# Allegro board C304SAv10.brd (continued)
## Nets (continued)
GNDD: C1.2 C2.2 C3.2 C4.2 C5.1 C6.1 C7.1 C8.2 C9.2 C10.1 C11.1 C12.1 C13.1 C14.2 C15.1 C16.1 C17.1 C18.1 C19.1 C20.2 C21.2 C22.2 C23.2 C24.2 C25.2 C26.2 C27.2 C28.2 C29.2 C30.2 C31.2 C32.2 C33.2 C34.2 C35.2 C36.2 C37.2 C38.2 C39.2 C40.2 C41.2 C42.2 C43.2 C44.2 C45.2 C46.2 C47.2 C48.2 C49.2 C50.2 C51.2 C52.2 C53.2 C54.2 C55.2 C56.2 C57.2 C58.2 C59.2 C60.2 C61.2 C62.2 C63.2 C64.2 C65.2 C68.2 C69.2 C70.2 C71.1 C72.1 C73.2 C74.2 C75.2 C76.2 C77.2 C78.1 C79.1 C80.2 C81.2 C82.2 C83.2 C84.2 C85.2 C86.2 C87.2 C88.2 C89.2 C90.2 C91.2 C92.2 C93.2 C94.2 C95.2 C96.2 C97.2 C98.2 C99.2 C100.2 C101.2 C102.2 C103.2 C104.2 C105.2 C106.2 C107.2 C108.2 C109.2 C110.2 C111.2 C112.2 C113.2 C114.2 C115.2 C116.2 C117.2 C118.2 C119.2 C120.2 C121.2 C122.2 C123.2 C124.2 C125.2 C126.2 C127.2 C128.2 C129.2 C130.2 C131.2 C132.2 C134.2 C135.2 C136.2 C137.2 C138.2 C139.2 C140.2 C141.2 C142.2 C143.2 C148.2 C151.2 C154.2 C155.2 C156.2 C157.2 C160.2 C163.2 C164.2 C165.2 C168.2 C171.2 C172.2 C173.2 C176.2 C179.2 C182.2 C184.2 C185.2 C186.2 C187.2 C188.2 C189.2 C190.2 C191.2 C192.2 C193.2 C194.2 C195.2 C196.2 C197.2 C198.2 C199.2 C200.2 C201.2 C202.2 C203.2 C204.2 C205.2 C206.2 C207.2 C208.2 C209.2 C210.2 C211.2 C212.2 C213.2 C214.2 C215.1 C216.1 C217.1 C218.1 C219.2 C220.2 C222.2 C223.2 C380.2 C381.2 C382.2 C383.2 C384.2 C385.2 C386.2 C387.2 C388.2 CE1.2 CE2.2 CE3.2 CE4.2 CE11.2 D1.8(GND#8) D1.20(GND#20) D1.27(GND#27) D1.30(GNDPLL#30) D1.34(GNDOSC) D1.39(GNDPLL#39) D1.41(GND#41) D1.57(GND#57) D1.63(GND#63) D1.76(GND#76) D1.94(GND#94) D1.112(GND#112) D1.117(GND#117) D1.130(GND#130) D1.132(GND#132) D1.147(GND#147) D1.153(GND#153) D1.165(GND#165) D1.184(GND#184) D1.189(GND#189) D1.200(GND#200) D2.1(A0) D2.2(A1) D2.3(A2) D2.4(VSS) D2.7(TSET) D3.3(GND) D4.1(GND) D5.6(VSSQ#6) D5.12(VSSQ#12) D5.28(VSS#28) D5.41(VSS#41) D5.46(VSSQ#46) D5.52(VSSQ#52) D5.54(VSS#54) D6.6(VSSQ#6) D6.12(VSSQ#12) D6.28(VSS#28) D6.41(VSS#41) D6.46(VSSQ#46) D6.52(VSSQ#52) D6.54(VSS#54) D7.27(VSS#27) D7.46(VSS#46) D8.11(DGND#11) D8.17(DGND#17) D8.29(AGND#29) D8.35(AGND#35) D8.45(DGND#45) D9.AA2(GND#AA2) D9.AA9(GNDA#AA9) D9.AA20(GNDA#AA20) D9.AA27(GND#AA27) D9.AC6(GND#AC6) D9.AC9(GND#AC9) D9.AC13(GND#AC13) D9.AC16(GND#AC16) D9.AC20(GND#AC20) D9.AC23(GND#AC23) D9.AF1(GND#AF1) D9.AF28(GND#AF28) D9.AG2(GND#AG2) D9.AG5(GND#AG5) D9.AG9(GND#AG9) D9.AG13(GND#AG13) D9.AG16(GND#AG16) D9.AG20(GND#AG20) D9.AG24(GND#AG24) D9.AG27(GND#AG27) D9.B2(GND#B2) D9.B5(GND#B5) D9.B9(GND#B9) D9.B13(GND#B13) D9.B16(GND#B16) D9.B20(GND#B20) D9.B24(GND#B24) D9.B27(GND#B27) D9.C1(GND#C1) D9.C28(GND#C28) D9.F6(GND#F6) D9.F9(GND#F9) D9.F13(GND#F13) D9.F16(GND#F16) D9.F20(GND#F20) D9.F23(GND#F23) D9.H2(GND#H2) D9.H9(GNDA#H9) D9.H20(GNDA#H20) D9.H27(GND#H27) D9.J11(GND#J11) D9.J18(GND#J18) D9.K6(GND#K6) D9.K10(GND#K10) D9.K12(GND#K12) D9.K14(GND#K14) D9.K16(GND#K16) D9.K18(GND#K18) D9.K20(GND#K20) D9.K23(GND#K23) D9.L9(GND#L9) D9.L11(GND#L11) D9.L13(GND#L13) D9.L15(GND#L15) D9.L17(GND#L17) D9.L19(GND#L19) D9.M10(GND#M10) D9.M12(GND#M12) D9.M14(GND#M14) D9.M16(GND#M16) D9.M18(GND#M18) D9.M20(GND#M20) D9.M22(MSEL2) D9.N2(GND#N2) D9.N6(GND#N6) D9.N9(GND#N9) D9.N11(GND#N11) D9.N13(GND#N13) D9.N15(GND#N15) D9.N17(GND#N17) D9.N19(GND#N19) D9.N22(MSEL0) D9.N23(GND#N23) D9.N27(GND#N27) D9.P10(GND#P10) D9.P12(GND#P12) D9.P14(GND#P14) D9.P16(GND#P16) D9.P18(GND#P18) D9.P20(GND#P20) D9.P22(MSEL3) D9.P23(MSEL1) D9.R8(NCE) D9.R9(GND#R9) D9.R11(GND#R11) D9.R13(GND#R13) D9.R15(GND#R15) D9.R17(GND#R17) D9.R19(GND#R19) D9.T2(GND#T2) D9.T6(GND#T6) D9.T10(GND#T10) D9.T12(GND#T12) D9.T14(GND#T14) D9.T16(GND#T16) D9.T18(GND#T18) D9.T20(GND#T20) D9.T23(GND#T23) D9.T27(GND#T27) D9.U9(GND#U9) D9.U11(GND#U11) D9.U13(GND#U13) D9.U15(GND#U15) D9.U17(GND#U17) D9.U19(GND#U19) D9.V10(GND#V10) D9.V12(GND#V12) D9.V14(GND#V14) D9.V16(GND#V16) D9.V18(GND#V18) D9.V20(GND#V20) D9.W6(GND#W6) D9.W9(GND#W9) D9.W11(GND#W11) D9.W13(GND#W13) D9.W15(GND#W15) D9.W17(GND#W17) D9.W19(GND#W19) D9.W23(GND#W23) D9.Y11(GND#Y11) D9.Y18(GND#Y18) D11.3(VEE#3) D11.17(VEE#17) D12.3(VEE#3) D12.17(VEE#17) D13.3(VEE#3) D13.17(VEE#17) D14.3(VEE#3) D14.17(VEE#17) D15.3(GND#3) D15.6(GND#6) D16.1(GND) D18.15(GND) D28.3(SGND) D28.10(PGND#10) D28.11(PGND#11) D28.EP D31.4(GND#4) D31.10(GND#10) D31.15(GND#15) D31.21(GND#21) D31.28(GND#28) D31.34(GND#34) D31.39(GND#39) D31.45(GND#45) D32.4(GND#4) D32.10(GND#10) D32.15(GND#15) D32.21(GND#21) D32.28(GND#28) D32.34(GND#34) D32.39(GND#39) D32.45(GND#45) D33.1(A0) D33.2(A1) D33.3(A2) D33.4(VSS) D33.7(TEST) G1.3(GND) G2.3(GND#3) G2.4(GND#4) G2.5(GND#5) G3.3(GND) G4.2(GND) GND.1(TP) HL5.2(CATHODE) HL6.2(CATHODE) HL7.2(CATHODE) HL8.2(CATHODE) R1.2 R2.2 R3.2 R10.1 R14.1 R16.1 R28.1 R44.2 R47.2 R51.2 R53.2 R54.1 R68.2 R79.2 R82.2 R114.2 R115.2 R116.2 R117.2 R120.2 R131.1 R133.1 R134.2 R140.1 VD1.1(ANODE) X1.A20 X1.A21 X1.A30 X1.B4 X1.B8 X1.B20 X1.B21 X1.B22 X1.B26 X1.B30 X1.C6 X1.C8 X1.C9 X1.C17 X1.C20 X1.C21 X1.C22 X1.C26 X1.C30 X3.2 X4.1 X5.2 X5.4 X5.6 X5.8 X5.10 X5.14 X6.9(GND#9) X6.10(GND#10) X7.2 X7.10 X8.1(GND) X9.1(GND) X10.1(GND) X11.1(GND) X12.1(GND) X13.1(GND) X14.2(GND#2) X14.3(GND#3) X14.4(GND#4) X15.2(GND#2) X15.3(GND#3) X15.4(GND#4) X16.2(GND#2) X16.3(GND#3) X16.4(GND#4) X17.2(GND#2) X17.3(GND#3) X17.4(GND#4) X18.2
27M_FPGA: D9.Y28(CLK7/DIFFCLK_3N) R69.2
706MR: C9.1 D1.74(PA28) D3.1(M\R\) R11.1 X3.1
706WDI: D1.73(PA27) D3.6(WDI)
ASI_OUTN1: C150.1 D9.D1(IO/DIFFIO_L2N) R76.2
ASI_OUTN2: C162.1 D9.G1(IO/DIFFIO_L11N) R93.2
ASI_OUTN3: C170.1 D9.W1(IO/DIFFIO_L24N) R101.2
ASI_OUTN4: C178.1 D9.AC1(IO/DIFFIO_L27N) R109.2
ASI_OUTP1: C149.1 D9.D2(IO/DIFFIO_L2P) R76.1
ASI_OUTP2: C161.1 D9.G2(IO/DIFFIO_L11P) R93.1
ASI_OUTP3: C169.1 D9.W2(IO/DIFFIO_L24P) R101.1
ASI_OUTP4: C177.1 D9.AC2(IO/DIFFIO_L27P) R109.1
AT91_CAS: D1.177(CAS) D5.17(C\A\S\) D6.17(C\A\S\)
AT91_NCS0: D1.166(NCS0) D7.26(C\E\)
AT91_NCS1: D1.167(NCS1/SDCS) D5.19(C\S\) D6.19(C\S\)
AT91_NCS7: D1.14(NCS7) D9.AG26(IO/DIFFIO_B41P)
AT91_NRD: D1.170(NRD) D7.28(O\E\) D9.AH11(IO/DIFFIO_B19N)
AT91_NWE: D1.171(NWE) D7.11(W\E\) D9.AG12(IO/DIFFIO_B21P)
AT91_RAS: D1.176(RAS) D5.18(R\A\S\) D6.18(R\A\S\)
AT91_SDCKE: D1.175(SDCKE) D5.37(CKE) D6.37(CKE)
AT91_SDCLK: D1.174(SDCK) R35.2 R36.2
AT91_SDWE: D1.178(SDWE) D5.16(W\E\) D6.16(W\E\)
AT91A0: D1.133(N0/NBS0) D5.15(LDQM)
AT91A1: D1.134(N1/NBS2) D6.15(LDQM) D7.25(A0) D9.W27(IO/DIFFIO_R25N)
AT91A2: D1.135(A2) D5.23(A0) D6.23(A0) D7.24(A1) D9.AC27(IO/DIFFIO_R31P)
AT91A3: D1.136(A3) D5.24(A1) D6.24(A1) D7.23(A2) D9.AC28(IO/DIFFIO_R31N)
AT91A4: D1.137(A4) D5.25(A2) D6.25(A2) D7.22(A3) D9.AB27(IO/DIFFIO_R28P)
AT91A5: D1.138(A5) D5.26(A3) D6.26(A3) D7.21(A4) D9.AB28(IO/DIFFIO_R28N)
AT91A6: D1.139(A6) D5.29(A4) D6.29(A4) D7.20(A5) D9.AD28(IO/DIFFIO_R33N)
AT91A7: D1.140(A7) D5.30(A5) D6.30(A5) D7.19(A6) D9.AD27(IO/DIFFIO_R33P)
AT91A8: D1.141(A8) D5.31(A6) D6.31(A6) D7.18(A7) D9.AE28(IO/DIFFIO_R34N)
AT91A9: D1.142(A9) D5.32(A7) D6.32(A7) D7.8(A8) D9.AE27(IO/DIFFIO_R34P)
AT91A10: D1.143(A10) D5.33(A8) D6.33(A8) D7.7(A9) D9.AD24(IO/DIFFIO_B40N)
AT91A11: D1.145(A11) D5.34(A9) D6.34(A9) D7.6(A10)
AT91A12: D1.148(A12) D7.5(A11)
AT91A13: D1.149(A13) D5.35(A11) D6.35(A11) D7.4(A12)
AT91A14: D1.150(A14) D5.36(NC1) D6.36(NC1) D7.3(A13)
AT91A15: D1.151(A15) D7.2(A14)
AT91A16: D1.154(A16/BA0) D5.20(BA0) D6.20(BA0) D7.1(A15)
AT91A17: D1.155(A17/BA1) D5.21(BA1) D6.21(BA1) D7.48(A16)
AT91A18: D1.156(A18) D7.17(A17)
AT91A19: D1.157(A19) D7.16(A18)
AT91A20: D1.158(A20) D7.9(NC/A19)
AT91A21: D1.159(A21) D7.10(NC/A20)
AT91A22: D1.160(A22) D7.13(NC/A21)
AT91D0: D1.179(D0) D5.2(DQ0) D7.29(DQ0) D9.AH12(IO/DIFFIO_B21N)
AT91D1: D1.180(D1) D5.4(DQ1) D7.31(DQ1) D9.AG17(IO/DIFFIO_B24P)
AT91D2: D1.181(D2) D5.5(DQ2) D7.33(DQ2) D9.AH17(IO/DIFFIO_B24N)
AT91D3: D1.182(D3) D5.7(DQ3) D7.35(DQ3) D9.AF18(IO/DIFFIO_B31N)
AT91D4: D1.185(D4) D5.8(DQ4) D7.38(DQ4) D9.AH18(IO/DIFFIO_B27N)
AT91D5: D1.186(D5) D5.10(DQ5) D7.40(DQ5) D9.AG18(IO/DIFFIO_B27P)
AT91D6: D1.187(D6) D5.11(DQ6) D7.42(DQ6) D9.AG23(IO/DIFFIO_B33P)
AT91D7: D1.190(D7) D5.13(DQ7) D7.44(DQ7) D9.AG22(IO/DIFFIO_B32P)
AT91D8: D1.191(D8) D5.42(DQ8) D7.30(DQ8) D9.AH19(IO/DIFFIO_B28N)
AT91D9: D1.192(D9) D5.44(DQ9) D7.32(DQ9) D9.AG19(IO/DIFFIO_B28P)
AT91D10: D1.193(D10) D5.45(DQ10) D7.34(DQ10) D9.AH21(IO/DIFFIO_B30N)
AT91D11: D1.194(D11) D5.47(DQ11) D7.36(DQ11) D9.AG21(IO/DIFFIO_B30P)
AT91D12: D1.195(D12) D5.48(DQ12) D7.39(DQ12) D9.AH22(IO/DIFFIO_B32N)
AT91D13: D1.196(D13) D5.50(DQ13) D7.41(DQ13) D9.AH23(IO/DIFFIO_B33N)
AT91D14: D1.197(D14) D5.51(DQ14) D7.43(DQ14) D9.AH25(IO/DIFFIO_B39N)
AT91D15: D1.198(D15) D5.53(DQ15) D7.45(DQ15) D9.AG25(IO/DIFFIO_B39P)
AT91D16: D1.201(D16) D6.2(DQ0)
AT91D17: D1.202(D17) D6.4(DQ1)
AT91D18: D1.203(D18) D6.5(DQ2)
AT91D19: D1.204(D19) D6.7(DQ3)
AT91D20: D1.205(D20) D6.8(DQ4)
AT91D21: D1.206(D21) D6.10(DQ5)
AT91D22: D1.207(D22) D6.11(DQ6)
AT91D23: D1.208(D23) D6.13(DQ7)
AT91D24: D1.1(D24) D6.42(DQ8)
AT91D25: D1.2(D25) D6.44(DQ9)
AT91D26: D1.3(D26) D6.45(DQ10)
AT91D27: D1.4(D27) D6.47(DQ11)
AT91D28: D1.5(D28) D6.48(DQ12)
AT91D29: D1.6(D29) D6.50(DQ13)
AT91D30: D1.9(D30) D6.51(DQ14)
AT91D31: D1.10(D31) D6.53(DQ15)
AT91NBS1: D1.172(NBS1) D5.39(UDQM)
AT91NBS3: D1.173(NBS3) D6.39(UDQM)
AT91NRST: C2.1 D1.115(NRST) D3.7(RESET) R9.2 X5.12
AT91NTRST: D1.110(NTRST) R29.1 X5.3
AT91SDA10: D1.144(SDA10) D5.22(A10/AP) D6.22(A10/AP)
AT91TCK: D1.108(TCK) R32.1 X5.9
AT91TDI: D1.106(TDI) R30.1 X5.5
AT91TDO: D1.107(TDO) R34.1 X5.11
AT91TMS: D1.109(TMS) R31.1 X5.7
BOARDDET_0: R1.1 X1.A32
BOARDDET_1: R2.1 X1.B32
BOARDDET_2: R3.1 X1.C32
E3.3VA: C75.1 C76.1 C77.1 D8.36(AVDD33) D8.48(DVDD33#48) L2.2
ENETCOL: D1.100(ECOL) D8.1(COL)
ENETCRS: D1.53(ECRS) D8.23(CRS)
ENETMDC: D1.59(EMDC) D8.25(MDC)
ENETMDIO: D1.60(EMDIO) D8.26(MDIO) R8.2
ENETRX0: D1.54(ERX0) D8.21(RXD0)
ENETRX1: D1.55(ERX1) D8.20(RXD1)
ENETRX2: D1.97(ERX2) D8.19(RXD2)
ENETRX3: D1.98(ERX3) D8.18(RXD3)
ENETRX+: D8.31(TPRX+) R55.2 T1.6(RD+)
ENETRX-: D8.30(TPRX-) R52.2 T1.8(RD-)
ENETRXCK: D1.101(ERXCK) D8.16(RXC)
ENETRXDV: D1.99(ERXDV) D8.22(RXDV)
ENETRXER: D1.58(ERXER) D8.24(RXER/FXEN) R140.2
ENETTX0: D1.51(ETX0) D8.6(TXD0)
ENETTX1: D1.52(ETX1) D8.5(TXD1)
ENETTX2: D1.92(ETX2) D8.4(TXD2)
ENETTX3: D1.95(ETX3) D8.3(TXD3)
ENETTX+: D8.34(TPTX+) R57.2 T1.1(TD+)
ENETTX-: D8.33(TPTX-) R56.2 T1.3(TD-)
ENETTXCK: D1.49(ETXCK) D8.7(TXCLK)
ENETTXEN: D1.50(ETXEN) D8.2(TXEN)
F_LED0: D9.AB23(IO/RDN3) HL10.2(CATHODE)
F_LED1: D9.AC26(IO/DIFFIO_R35P) HL11.2(CATHODE)
F_LED2: D9.AC24(IO/DIFFIO_R36P) HL12.2(CATHODE)
F_LED3: D9.AD26(IO/DIFFIO_R35N) HL9.2(CATHODE)
FPGA_CONDONE: D9.P24(CONF_DONE) R65.1 R121.2 R129.1
FPGA_DATA0: D9.N7(IO/DATA0) R124.2 R126.1 R136.1
FPGA_DCLK: D9.P3(DCLK) R123.2 R128.1 R135.1
FPGA_INT: D1.45(IRQ5/PA3) D9.AH26(IO/DIFFIO_B41N)
FPGA_NCONFIG: C220.1 D9.P4(NCONFIG) R122.2 R127.1 R146.1
FPGA_NSTATUS: D9.M6(NSTATUS) R64.1 R125.2 R130.1
FPGA_TCK: D9.P5(TCK) R68.1 X7.1
FPGA_TDI: D9.P7(TDI) R67.1 X7.9
FPGA_TDO: D9.P6(TDO) X7.3
FPGA_TMS: D9.P8(TMS) R66.1 X7.5
HS_ADDB_A0: D9.U27(IO_3_B5) X1.A19
HS_ADDB_A1: D9.V28(IO/DIFFIO_R24N) X1.B19
HS_ADDB_A2: D9.V27(IO/DIFFIO_R24P) X1.C19
HS_ADDB_A3: D9.R28(IO/DIFFIO_R18N) X1.A18
HS_ADDB_A4: D9.R27(IO/DIFFIO_R18P) X1.B18
HS_ADDB_A5: D9.U28(IO/DIFFIO_R21N) X1.C18
HS_ADDB_A6: D9.M27(IO/DIFFIO_R14P) X1.A17
HS_ADDB_A7: D9.M28(IO/DIFFIO_R14N) X1.B17
HS_DATB_D0: D9.L26(IO_1_B6) X1.A16
HS_DATB_D1: D9.M25(IO/DIFFIO_R13P) X1.B16
HS_DATB_D2: D9.M26(IO/DIFFIO_R13N) X1.C16
HS_DATB_D3: D9.K25(IO/DIFFIO_R7P) X1.A15
HS_DATB_D4: D9.K26(IO/DIFFIO_R7N) X1.B15
HS_DATB_D5: D9.L25(IO_2_B6) X1.C15
HS_DATB_D6: D9.D25(IO/DIFFIO_T38N) X1.A14
HS_DATB_D7: D9.C25(IO/DIFFIO_T38P) X1.B14
HS_DATB_D8: D9.C26(IO/DIFFIO_T42N) X1.C14
HS_DATB_D9: D9.D22(IO/DIFFIO_T41N) X1.A13
HS_DATB_D10: D9.D24(IO/DIFFIO_T36P) X1.B13
HS_DATB_D11: D9.C24(IO/DIFFIO_T36N) X1.C13
HS_DATB_D12: D9.A26(IO/DIFFIO_T40N) X1.A12
HS_DATB_D13: D9.D21(IO/DIFFIO_T35P) X1.B12
HS_DATB_D14: D9.C22(IO/DIFFIO_T35N) X1.C12
HS_DATB_D15: D9.B26(IO/DIFFIO_T42P) X1.A11
HS_ENC_RXD: D9.A23(IO/DIFFIO_T37N) X1.A9
HS_ENC_SCK: D9.B25(IO_1_B7) X1.B9
HS_ENC_TXD: D9.B23(IO/DIFFIO_T37P) X1.A8
HS_FPGA_CS: D9.D20(IO/DIFFIO_T30P) X1.A10
HS_FPGA_INT: D9.W28(IO/DIFFIO_R25P) R120.1 X1.A5
HS_FPGA_RD: D9.A25(IO/DIFFIO_T40P) X1.B10
HS_FPGA_WR: D9.B21(IO/DIFFIO_T33P) X1.C11
HS_HPI_HBE1: D9.E21(IO/DIFFIO_T39N) X1.C10
HS_HPI_HCS: D9.E22(IO/DIFFIO_T41P) X1.B11
HS_HPI_HINT: D9.D19(IO/DIFFIO_T29P) X1.B5
HS_HPI_HRDY: D9.C19(IO/DIFFIO_T29N) X1.C5
HS_SCL: D9.AH3(IO/DIFFIO_B4P) D33.6(SCL) R144.2 X1.C31
HS_SDA: D9.AG3(IO/DIFFIO_B3N) D33.5(SDA) R143.2 X1.B31
HS_TS1_CLK: D32.14(B9) X1.A26
HS_TS1_D0: D32.2(B0) X1.A29
HS_TS1_D1: D32.3(B1) X1.B29
HS_TS1_D2: D32.5(B2) X1.C29
HS_TS1_D3: D32.6(B3) X1.A28
HS_TS1_D4: D32.8(B4) X1.B28
HS_TS1_D5: D32.9(B5) X1.C28
HS_TS1_D6: D32.11(B6) X1.A27
HS_TS1_D7: D32.12(B7) X1.B27
HS_TS1_VALID: D32.13(B8) X1.C27
HS_TS2_CLK: D31.14(B9) X1.A22
HS_TS2_D0: D31.2(B0) X1.A25
HS_TS2_D1: D31.3(B1) X1.B25
HS_TS2_D2: D31.5(B2) X1.C25
HS_TS2_D3: D31.6(B3) X1.A24
HS_TS2_D4: D31.8(B4) X1.B24
HS_TS2_D5: D31.9(B5) X1.C24
HS_TS2_D6: D31.11(B6) X1.A23
HS_TS2_D7: D31.12(B7) X1.B23
HS_TS2_VALID: D31.13(B8) X1.C23
JTAGSEL: D1.105(JTAGSEL) R10.2
KEY0: D1.17(PC0) R26.2 R119.2
KEY5: D1.24(PC5) R27.2 R118.2
LED0: D1.121(PB26) HL1.2(CATHODE)
LED1: D1.122(PB27) HL2.2(CATHODE)
LED2: D1.123(FIQ/PB28) HL3.2(CATHODE)
LED3: D1.124(IRQ0/PB29) HL4.2(CATHODE)
LED_100M: D8.13(LED3/PHYAD3) R53.1 X6.13(LAN+)
LED_LINK: D8.9(LED0/PHYAD0) R58.2 R59.1
LOOP0: D9.AH14(CLK14/DIFFCLK_6N) R72.2
LOOP1: D9.B15(CLK9/DIFFCLK_5P) R70.1
LOOP2: D9.J2(CLK0/DIFFCLK_0P) R73.1
LOOP3: D9.J27(CLK4/DIFFCLK_2P) R71.2
LOOP4: D9.AG15(CLK13/DIFFCLK_7P) R74.2
LOOP5: D9.B14(CLK11/DIFFCLK_4P) R75.2
OE1: D9.AH10(IO/DIFFIO_B16N) D32.25(O\E\2\) D32.48(O\E\1\) R163.1
OE2: D9.Y25(IO/DIFFIO_R27P) D31.25(O\E\2\) D31.48(O\E\1\) R157.1
PWFBIN: C82.1 C83.1 C84.1 D8.8(PWFBIN) L3.2
PWFBOUT: C80.1 C81.1 D8.32(PWFBOUT) L3.1
REV: D9.AG4(IO/DIFFIO_B5P) X1.A31
RST8201: D1.67(RTS0/PA21) D8.42(RESETB) R43.2
RXD_232: D1.68(RXD2/PA22) R131.2 R132.1
SCL: D2.6(SCL) R5.2 R7.1
SDA: D2.5(SDA) R4.2 R6.1
TR1: D9.AG11(IO/DIFFIO_B19P) D32.1(T/R\1\) D32.24(T/R\2\) R161.2
TR2: D9.AB26(IO/DIFFIO_R30N) D31.1(T/R\1\) D31.24(T/R\2\) R156.2
TS1_CLK: D9.AE4(IO/DIFFIO_B3P) D32.35(A9) R138.1
TS1_D0: D9.AG10(IO/DIFFIO_B16P) D32.47(A0)
TS1_D1: D9.AG8(IO/DIFFIO_B12P) D32.46(A1)
TS1_D2: D9.AH8(IO/DIFFIO_B12N) D32.44(A2)
TS1_D3: D9.AH7(IO/DIFFIO_B9N) D32.43(A3)
TS1_D4: D9.AG7(IO/DIFFIO_B9P) D32.41(A4)
TS1_D5: D9.AH6(IO/DIFFIO_B7N) D32.40(A5)
TS1_D6: D9.AG6(IO/DIFFIO_B7P) D32.38(A6)
TS1_D7: D9.AH4(IO/DIFFIO_B5N) D32.37(A7)
TS1_VALID: D9.AF4(IO/DIFFIO_B2N) D32.36(A8) R141.1
TS2_CLK: D9.F26(IO/DIFFIO_R4P) D31.35(A9) R137.1
TS2_D0: D9.Y26(IO/DIFFIO_R27N) D31.47(A0)
TS2_D1: D9.Y24(IO/DIFFIO_R32N) D31.46(A1)
TS2_D2: D9.L28(IO/DIFFIO_R12N) D31.44(A2)
TS2_D3: D9.L27(IO/DIFFIO_R12P) D31.43(A3)
TS2_D4: D9.K28(IO/DIFFIO_R10N) D31.41(A4)
TS2_D5: D9.K27(IO/DIFFIO_R10P) D31.40(A5)
TS2_D6: D9.J26(IO/DIFFIO_R9N) D31.38(A6)
TS2_D7: D9.J25(IO/DIFFIO_R9P) D31.37(A7)
TS2_VALID: D9.H26(IO/DIFFIO_R4N) D31.36(A8) R142.1
TXD_232: D1.69(TXD2/PA23) D18.11(T1IN)
N05536: D1.113(TST0) R14.2
N05538: D1.114(TST1) R16.2
N07829: C12.2 D1.32(XIN) G1.2
N08193: C8.1 D1.31(XOUT) G1.1
N08983: C17.2 D1.36(XIN32) G2.1
N09392: C14.1 D1.35(XOUT32) G2.2
N27514: C7.2 D1.38(PLLRCB) R15.2
N29811: C5.2 D1.29(PLLRCA) R13.2
N30543: C19.2 R23.1
N30727: C6.2 R13.1
N31299: C13.2 R17.1
N32037: C16.2 R22.1
N43106: D1.25(NWAIT) R24.2
N44506: D1.79(DTXD/BMS) R28.2
N118230: C46.1 D5.38(CLK) R35.1
N119725: C47.1 D6.38(CLK) R36.1
N293237: C68.1 D8.47(X2) G3.1
N294666: C69.1 D8.46(X1) G3.2
N300423: D8.44(MII/SNIB/RTT3) R45.1
N301796: D8.43(ISOLATE) R44.1
N302871: D8.41(LDPS) R46.1
N304860: D8.40(RPTR) R47.1
N306022: D8.39(SPEED) R48.1
N306487: D8.38(DUPLEX) R49.1
N307425: D8.37(ANE) R50.1
N316976: D8.28(RTSET) R51.1
N334633: C72.2 T1.5(RPCT1) T1.7(CTRD)
N338225: C71.2 R52.1 R55.1
N339802: C78.2 R56.1 R57.1
N340684: C79.2 T1.2(CTTD)
N359542: R54.2 X6.14(LAN-)
N360160: R59.2 X6.12(LINK-)
N372108: C85.1 R60.2 R61.2
N373239: C86.1 R62.2 R63.2
N373968: R60.1 T1.13(RPCT2) T1.15(CTTX)
N375126: R61.1 T1.10(CTRX)
N377910: T1.9(RX-) X6.6
N379080: T1.11(RX+) X6.3
N380455: T1.14(TX-) X6.2
N381046: T1.16(TX+) X6.1
N382236: R62.1 X6.7 X6.8
N383434: R63.1 X6.4 X6.5
N9171469: D1.71(TWD/PA25) R4.1
N9173252: D1.72(TWCK/PA26) R5.1
N9248576: C3.1 D3.8(WDO) R12.2
N9251784: R11.2 R12.1 X2.1
N14977744: C10.2 R15.1
N16808315: R26.1 R27.1 X4.2
N16825915: HL3.1(ANODE) R20.2
N16825917: HL4.1(ANODE) R21.2
N16825919: HL1.1(ANODE) R18.2
N16825921: HL2.1(ANODE) R19.2
N16864209: D11.4(RREF) R85.1
N16868983: C148.1 R77.1 R78.2
N16869942: C149.2 D11.1(SDI) R77.2
N16872327: C150.2 D11.2(\\S\D\I\) R78.1
N16882305: C153.1 L6.2 R89.2
N16882306: C152.1 L5.2 R88.2
N16882340: D11.11(\\S\D\O) L6.1 R87.2 R89.1
N16882850: D11.12(SDO) L5.1 R86.2 R88.1
N16891295: C152.2 X14.1(IN)
N16896654: C160.1 R92.2 R94.1
N16896672: C159.1 L8.2 R91.2
N16896674: C158.1 L7.2 R90.2
N16896676: D12.11(\\S\D\O) L8.1 R91.1 R97.2
N16896680: D12.12(SDO) L7.1 R90.1 R96.2
N16896682: C161.2 D12.1(SDI) R94.2
N16896719: C162.2 D12.2(\\S\D\I\) R92.1
N16896823: D12.4(RREF) R95.1
N16896879: C158.2 X15.1(IN)
N16897851: C168.1 R100.2 R102.1
N16897869: C167.1 L10.2 R99.2
N16897871: C166.1 L9.2 R98.2
N16897873: D13.11(\\S\D\O) L10.1 R99.1 R105.2
N16897877: D13.12(SDO) L9.1 R98.1 R104.2
N16897879: C169.2 D13.1(SDI) R102.2
N16897916: C170.2 D13.2(\\S\D\I\) R100.1
N16898020: D13.4(RREF) R103.1
N16898076: C166.2 X16.1(IN)
N16905369: C176.1 R108.2 R110.1
N16905379: C174.1 L12.2 R106.2
N16905381: C175.1 L11.2 R107.2
N16905399: D14.11(\\S\D\O) L12.1 R106.1 R113.2
N16905403: D14.12(SDO) L11.1 R107.1 R112.2
N16905405: C177.2 D14.1(SDI) R110.2
N16905419: C178.2 D14.2(\\S\D\I\) R108.1
N16905542: D14.4(RREF) R111.1
N16905596: C175.2 X17.1(IN)
N16942301: C133.1 D15.4(FB) R79.1 R80.2
N16942335: D15.2(VOUT) L4.1 VD1.2(CATHODE)
N16942461: D15.5(O\N\) R82.1
N16942511: HL6.1(ANODE) R81.2
N16948660: HL7.1(ANODE) R83.2
N16978661: C153.2 R114.1
N16984500: C167.2 R116.1
N16986460: C174.2 R117.1
N17223725: D1.84(PB4) R130.2
N17224583: D1.85(PB5) R129.2
N17225441: D1.86(PB6) R128.2
N17226299: D1.87(PB7) R127.2
N17227157: D1.88(PB8) R126.2
N17239189: R121.1 X1.A7
N17239190: R122.1 X1.A6
N17245894: HL8.1(ANODE) R84.2
N17253757: R123.1 X1.B7
N17253758: R124.1 X1.B6
N17260250: R125.1 X1.C7
N17338881: D18.12(R1OUT) R132.2
N17347251: D18.10(T2IN) R133.2
N17354165: C180.1 D18.5(C2-)
N17355489: C180.2 D18.4(C2+)
N17356153: C181.1 D18.3(C1-)
N17358824: C181.2 D18.1(C1+)
N17377653: C183.1 D18.2(V+)
N17383951: C184.1 D18.6(V-)
N17388205: D18.14(T1OUT) X18.1
N17389740: D18.13(R1IN) X18.3
N17391601: D18.7(T2OUT) R134.1
N17552645: C219.1 D28.4(SS)
N17552715: D28.8(SW#8) D28.9(SW#9) L13.1
N17574922: C187.1 R136.2
N17574956: G4.3(CLK_OUT) R69.1
N17575063: C186.1 R135.2
N17877624: D9.H24(IO/DIFFIO_R1N) R71.1
N17882638: D9.G15(IO_4_B7) R70.2
N17918549: C222.1 R142.2
N17918577: C223.1 R141.2
N17986390: D9.AE20(IO/DIFFIO_B36P) R74.1
N18029824: D9.AB13(IO/DIFFIO_B20N) R72.1
N18049270: D9.C13(IO/DIFFIO_T22N) R75.1
N18128293: C188.1 R137.2
N18128321: C189.1 R138.2
N18384691: HL12.1(ANODE) R139.2
N18384693: HL9.1(ANODE) R25.2
N18384695: HL10.1(ANODE) R41.2
N18384697: HL11.1(ANODE) R42.2
N18408270: HL5.1(ANODE) R33.2
N168966681: C159.2 R115.1
N176021771: D9.H6(IO1_B1) R73.2

Pads without a net: D1 11 12 13 15 16 18 21 22 23 42 43 44 46 47 48 61 64 65 66 70 77 78 80 81 82 83 89 90 91 96 102 103 104 118 119 120 125 126 127 128 161 162 163 168 169; D3 4 5; D5 40; D6 40; D7 12 14 15 47; D8 10 12 15 27; D9 A3 A4 A6 A7 A8 A10 A11 A12 A14 A15 A17 A18 A19 A21 A22 AA3 AA4 AA5 AA6 AA7 AA8 AA10 AA12 AA13 AA14 AA15 AA16 AA17 AA19 AA21 AA22 AA23 AA24 AA25 AA26 AB1 AB2 AB3 AB4 AB5 AB6 AB7 AB8 AB9 AB10 AB11 AB12 AB14 AB15 AB16 AB17 AB18 AB19 AB20 AB21 AB22 AB24 AB25 AC3 AC4 AC5 AC7 AC8 AC10 AC11 AC12 AC14 AC15 AC17 AC18 AC19 AC21 AC22 AC25 AD1 AD2 AD3 AD4 AD5 AD7 AD8 AD10 AD11 AD12 AD14 AD15 AD17 AD18 AD19 AD21 AD22 AD25 AE1 AE2 AE3 AE5 AE6 AE7 AE8 AE9 AE10 AE11 AE12 AE13 AE14 AE15 AE16 AE17 AE18 AE19 AE21 AE22 AE23 AE24 AE25 AE26 AF2 AF3 AF5 AF6 AF7 AF8 AF9 AF10 AF11 AF12 AF13 AF14 AF15 AF16 AF17 AF19 AF20 AF21 AF22 AF23 AF24 AF25 AF26 AF27 AG14 AH15 B3 B4 B6 B7 B8 B10 B11 B12 B17 B18 B19 B22 C2 C3 C4 C5 C6 C7 C8 C9 C10 C11 C12 C14 C15 C16 C17 C18 C20 C21 C23 C27 D3 D4 D5 D6 D7 D8 D9 D10 D11 D12 D13 D14 D15 D16 D17 D18 D23 D26 D27 D28 E1 E2 E3 E4 E5 E7 E8 E10 E11 E12 E14 E15 E17 E18 E19 E24 E25 E26 E27 E28 F1 F2 F3 F4 F5 F7 F8 F10 F11 F12 F14 F15 F17 F18 F19 F21 F22 F24 F25 F27 F28 G3 G4 G5 G6 G7 G8 G9 G10 G11 G12 G13 G14 G16 G17 G18 G19 G20 G21 G22 G23 G24 G25 G26 G27 G28 H3 H4 H5 H7 H8 H10 H12 H13 H14 H15 H16 H17 H19 H21 H22 H23 H25 J1 J3 J4 J5 J6 J7 J10 J12 J13 J14 J15 J16 J17 J19 J22 J23 J24 J28 K1 K2 K3 K4 K7 K8 K21 K22 L1 L2 L3 L4 L5 L6 L7 L8 L21 L22 L23 L24 M1 M2 M3 M4 M5 M7 M8 M21 M23 M24 N3 N4 N8 N21 N25 N26 P1 P2 P21 P25 P26 P27 P28 R1 R2 R3 R4 R5 R6 R7 R21 R22 R23 R24 R25 R26 T3 T4 T7 T8 T21 T22 T25 T26 U1 U2 U3 U4 U5 U6 U7 U8 U21 U22 U23 U24 U25 U26 V1 V2 V3 V4 V5 V6 V7 V8 V21 V22 V23 V24 V25 V26 W3 W4 W7 W8 W21 W22 W25 W26 Y1 Y2 Y3 Y4 Y5 Y6 Y7 Y10 Y12 Y13 Y14 Y15 Y16 Y17 Y19 Y22 Y23 Y27; D11 5 6 7 8 10 13 14 15 16; D12 5 6 7 8 10 13 14 15 16; D13 5 6 7 8 10 13 14 15 16; D14 5 6 7 8 10 13 14 15 16; D18 8 9; D28 5 12 13; D31 16 17 19 20 22 23 26 27 29 30 32 33; D32 16 17 19 20 22 23 26 27 29 30 32 33; G4 1; HOLE1 1; HOLE2 1; M1 1; M2 1; M3 1; M4 1; M5 1; M6 1; T1 4 12; X1 A3 A4 B3 C3 C4; X4 3 4; X7 6 7 8

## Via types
v1: diameter 0.55, hole 0.3, TOP to BOTTOM, 343 vias
v2: diameter 0.6, hole 0.3, TOP to BOTTOM, 395 vias
v3: diameter 0.8, hole 0.4, TOP to BOTTOM, 288 vias
v4: diameter 1, hole 0.5, TOP to BOTTOM, 22 vias

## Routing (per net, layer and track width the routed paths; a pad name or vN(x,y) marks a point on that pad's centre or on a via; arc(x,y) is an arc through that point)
+1.2VD: length 114.4
  TOP w0.15: D9.J9 22,79 13.3,79 UNK+1.2V.1 ; D9.U18 v1(30,88) D9.T17 ; D9.M11 v1(26,82) D9.N12
  TOP w0.3: D9.U12 v1(30,82) D9.T11 ; D9.V15 v1(32,86) D9.W16 ; v1(34,90) D9.Y20 D9.W20 ; D9.R16 v1(28,86) D9.P15 ; D9.P17 v1(28,88) D9.R18 ; v1(32,89) D9.V19 D9.U20 ; D9.K15 v1(24,85) D9.L14 ; D9.V17 v1(32,88) D9.W18 ; D9.R14 v1(28,84) D9.P13 ; D9.T9 v1(30,80) D9.U10 ; D9.P11 v1(28,82) D9.R12 ; v1(24,89) D9.K19 D9.J20 ; D9.R20 D9.T19 v1(30,89) ; D9.W12 v1(32,82) D9.V11 ; D9.M13 v1(26,84) D9.N14 ; D9.U14 v1(30,84) D9.T13 ; D9.W14 v1(32,84) D9.V13 ; D9.V9 v1(32,80) D9.W10 D9.Y9 ; D9.R10 v1(28,80) D9.P9 ; D9.U16 v1(30,86) D9.T15 ; D9.K13 v1(24,83) D9.L12 D9.K11 ; D9.N16 v1(26,86) D9.M15 D9.L16 ; D9.N18 v1(26,88) D9.M17 ; D9.K17 v1(24,88) D9.L18 D9.M19 D9.L20 ; D9.N20 D9.P19 v1(28,89) ; D9.J9 D9.K9 v1(24,80) D9.L10 ; D9.N10 v1(26,80) D9.M9
  TOP w0.4: D28.14 v1(40.65,50.75)
  TOP w0.5: R84.1 v1(29.9,56.8) ; v1(35.3,62.4) CE11.1 v1(38.2,62.4)
  BOTTOM w0.3: v1(32,82) 31.2,81.2 C93.1 ; C92.1 27.3,81.3 v1(28,82) ; C94.1 v1(30,86) C95.1 v1(28,86) C101.1 v1(26,86) C97.1 ; C91.1 v1(24,88) C106.1 v1(26,88) C102.1 v1(28,88) C99.1 v1(30,88) C100.1 v1(32,88) C89.1 ; v1(26,82) 25.3,81.3 C98.1 ; v1(24,83) 23.9,82.9 C104.1 ; v1(32,86) C105.1 C87.1 ; C108.1 C193.1 32.4,79.6 v1(32,80) 31.6,79.6 C192.1 30.4,79.6 v1(30,80) 29.6,79.6 C191.1 28.4,79.6 v1(28,80) 27.8,79.8 C88.1 26.2,79.8 v1(26,80) 25.7,79.7 C107.1 24.3,79.7 v1(24,80) 23.7,79.7 C103.1 ; C90.1 23.6,85 v1(24,85) ; C96.1 29.2,81.2 v1(30,82)
  BOTTOM w0.5: C218.2 38.22,62.42 v1(38.2,62.4) ; C216.2 v1(35.3,62.4)
  vias: v3(45.5,60.1) v3(46.9,60.1) v3(48.4,60.1) v3(50.1,60.1)
+1.8VA: length 32.6
  TOP w0.3: D1.37 v2(56.95,122.25) ; D1.28 54.35,126.75 v2(54.05,127.05) ; D1.33 v2(56.95,124.25)
  BOTTOM w0.3: R17.2 58.35,125.75 57.65,126.45 56.75,126.45 R23.2 54.95,127.05 v2(54.05,127.05) 53.85,127.05 C18.2 ; R17.2 C11.2 ; R17.2 58.05,125.35 v2(56.95,124.25) ; R22.2 C15.2
  BOTTOM w0.4: v2(56.95,124.25) v2(56.95,122.25) 57.05,122.25 R22.2
  BOTTOM w0.5: R22.2 58.35,120.65 56.85,119.15 56.85,117.45 C23.1 55.83,116.27 55.83,113.35 C22.1 L1.2 53.57,113.35
+1.8VD: length 45.7
  TOP w0.3: D1.152 v2(84.45,138.25) ; v4(41.65,142.35) 40.5,141.2 R33.1 ; D1.62 62.45,113.7 v2(62.3,113.85) ; D1.116 v2(84.5,120.25) ; D1.19 v2(54.15,131.25) ; D1.188 v2(67.95,141.35)
  TOP w1: D4.2 D4.4
  BOTTOM w0.3: UNK1.8V.1 43,115.9 v3(43.05,115.95) ; v2(84.5,120.25) C27.1 ; C24.1 67.5,141.8 v2(67.95,141.35) ; v2(62.3,113.85) 61.45,113.85 C26.1 ; C25.1 54.05,131.25 v2(54.15,131.25) ; C28.1 v2(84.45,138.25)
  BOTTOM w0.5: 47.73,113.15 47.72,113.15 C20.1 47.68,113.15 44.85,113.15 C21.1 44.1,113.1 43.05,114.15 v3(43.05,115.25) v3(43.05,115.95) ; 47.73,113.15 47.75,113.13 47.77,113.15 ; 47.73,113.15 47.77,113.15 ; v4(46.15,142.35) 46.15,141.3 45.92,141.07 C45.1 44.53,141.07 44.15,141.45 v4(44.15,142.35) ; 50.53,113.35 50.33,113.15 50.33,113.15 ; C44.1 v4(41.65,142.35) ; 50.33,113.15 47.77,113.15 ; 50.33,113.15 L1.1
  vias: v4(41.4,145.1) v4(41.4,143.65) v4(47.35,143.65) v4(48.45,144.95) v4(48.45,142.35)
+2.5VD: length 108.6
  TOP w0.3: v3(60,72.5) 60.7,73.2 R83.1 ; D9.T5 v1(30,75) ; D9.N5 v1(26,75) ; D9.J8 v1(22,78) ; D9.AA1 v1(34,72) ; D9.B1 v1(16,71) ; D9.Y8 v1(34,78) ; D9.W5 v1(32,75) ; D9.Y21 v1(34,91) ; D9.N1 v1(26,71) ; D9.K5 v1(24,75) ; D9.H1 v1(21.5,71) ; D9.J21 v1(22,91) ; D9.AG1 v1(40,72) ; D9.T1 v1(30,72)
  TOP w0.8: D16.4 D16.2
  MIDLAYER w0.3: v1(22,78) 23,79 23,90 v1(22,91) v1(34,91) 33,90 33,79 v1(34,78) ; v1(26,71) v1(21.5,71) v1(16,71)
  BOTTOM w0.15: UNK+2.5V.1 10.5,70.5 C203.1
  BOTTOM w0.3: C126.1 C205.1 C200.1 ; C126.1 21.3,71.2 v1(21.5,71) ; C126.1 20.1,71.1 C204.1 ; v1(22,78) C122.1 ; C206.1 C213.1 C123.1 39.6,71.6 v1(40,72) 40.4,71.6 C214.1 ; C202.1 C208.1 22.2,91.2 v1(22,91) ; C128.1 32.9,75 v1(32,75) ; C127.1 30.9,75 v1(30,75) ; v1(26,75) 25.9,74.9 C207.1 24.1,74.9 v1(24,75) 23.9,74.9 C121.1 C209.1 ; C199.1 C210.1 v1(34,78) ; v1(34,72) 34.4,71.6 C211.1 ; C125.1 16.5,70.5 v1(16,71) 15.5,70.5 C203.1 ; C212.1 34.2,91.2 v1(34,91) 33.8,91.2 C201.1 ; C124.1 30.4,71.6 v1(30,72)
  BOTTOM w0.5: C142.1 v3(54.9,72.6) ; v3(55,70.6) 54.52,70.12 C143.1
  vias: v3(56.6,72.6) v3(58.1,72.5) v3(60.3,70.7)
+3.3VD: length 376.8
  TOP w0.2: v1(30.7,185.8) 29.91,185 D31.31 ; v1(91.5,191.25) 91.55,191.21 D32.31 ; v2(84.55,126.75) D1.129 ; D31.7 36.89,192.72 v1(37.2,192.41) ; v2(84.55,127.75) D1.131 ; D32.7 v1(84.39,198.19) ; D31.42 v1(36.89,182.71) ; D32.18 v1(84.3,191.21) ; D32.42 v1(91.51,198.19) ; D31.18 v1(29.91,195.5)
  TOP w0.3: D9.E13 v1(18,84) ; D6.14 v3(58.25,168.25) ; v2(53.45,119.7) 53.5,119.7 54.55,120.75 D1.40 ; D6.3 v3(61.95,159.45) 62.65,159.45 C54.1 ; D9.AA28 v1(35,99) ; D1.146 v2(84.55,135.25) ; D9.A16 v1(15,87) ; D1.164 v2(79.95,141.35) ; v2(71.3,195.9) 71.4,196 D7.37 ; D5.9 v2(81.65,164.25) ; R46.2 v3(79.25,86.55) ; D5.14 v2(78.85,168.25) ; D9.AD23 v1(38,94) ; D9.A5 v1(15,76) ; D8.14 v2(64.55,90.55) ; D9.AA18 v1(35,88) ; D9.B28 v1(15,98) D9.A27 ; D1.93 v2(77.95,113.65) ; D9.AD9 v1(38,79) ; D9.AH27 v1(41,98) D9.AG28 ; v2(57.45,127.75) D1.26 ; D33.8 76.26,53.64 v1(75.66,53.04) ; D9.W24 v1(32,94) ; D9.AH5 v1(42,75) ; v2(87.35,117.85) 87.25,117.75 D1.111 ; D9.N24 v1(26,94) ; R48.2 v3(79.25,84.15) ; D9.AD16 v1(38,86) ; D5.27 81.45,178.65 v2(81.65,178.85) ; D9.H11 v1(21,82) ; D9.AD13 v1(38,84) ; D9.A2 v1(14,72) ; D9.AH9 v1(42,79) ; D5.49 v3(67.45,161.85) ; D9.AH16 v1(42,86) ; D9.T24 v1(29,94) ; D9.E16 v1(18,87) ; D9.A9 v1(15,80) ; D9.N28 v1(27,99) ; D6.49 v3(46.95,161.85) ; D9.A13 v1(14,84) ; D1.56 59.45,111.15 v2(59.65,110.95) ; D6.27 v3(61.15,178.65) ; D5.43 v3(67.25,166.65) ; D6.43 v3(46.95,166.65) ; D9.AD6 v1(38,76) ; R45.2 v3(79.25,90.15) ; D9.T28 v1(30,99) ; D5.3 v2(81.65,159.45) ; C53.1 v3(61.8,164.25) D6.9 ; D9.AH20 v1(42,91) ; D9.E20 v1(19,91) ; D9.H28 v1(21,99) ; D1.75 v2(68.95,113.65) ; D1.7 v2(56.85,137.25) ; D9.A20 v1(15,91) ; D5.1 v2(81.65,157.85) ; D9.K24 v1(24,94) ; D1.199 v2(62.45,141.35) ; R43.1 v3(79.25,87.75) ; D6.1 v3(61.95,157.85) C55.1 ; D9.AH13 v1(42,84) ; D9.E23 v1(19,94) ; D9.E6 v1(18,76) ; D9.AD20 v1(38,91) ; D1.183 v2(70.45,141.35) ; D9.AH24 v1(42,95) ; D9.H18 v1(21,88) ; D9.A24 v1(15,94) ; R49.2 v3(79.25,82.95) ; D9.AA11 v1(35,81) ; D9.AH2 v1(42,72) ; D9.E9 v1(18,80) ; R50.2 v3(79.25,81.75)
  TOP w0.4: R8.1 v2(64.4,80)
  TOP w0.5: 8.3,25.45 D11.9 v2(8.3,24.5) ; R144.1 R143.1 v2(81.4,48.9) ; D14.9 v2(56.3,24.5) ; v2(24.3,24.5) D12.9 ; G4.4 v3(13.4,117.3) ; C164.1 v3(47.35,24.55) ; C154.1 v3(15.35,24.55) ; C56.1 v3(61.3,154.45) ; D13.9 v2(40.3,24.6) ; C1.1 92.25,69.35 v3(91.65,69.35) D2.8 ; v3(79.7,55.8) C4.1 81.17,55.48 D3.2 ; C156.1 v3(31.35,24.55) ; R81.1 v3(11.3,142.5) ; C172.1 v3(63.35,24.55)
  TOP w1.15: 23.8,155.25 CE4.1 24.8,156.75 ; 9.18,155.47 CE2.1 8.15,157.78 ; 17.45,159.81 L4.2 ; L4.2 20.88,162.6 ; L4.2 14.02,162.6 ; CE3.1 17.05,157.6 ; CE3.1 15.8,155.35 ; CE3.1 18.3,155.35
  VCC w0.55: X5.13 89.83,80.63 ; X5.13 87.73,80.63 ; X5.13 88.78,81.68 ; X5.13 88.78,79.58 ; 79.44,68.74 X2.2 ; X2.2 80.45,69.75 ; X2.2 81.46,68.74 ; X2.2 80.45,67.73 ; X6.11 82.04,9.7 ; X6.11 80.99,10.75 ; X6.11 80.99,8.65 ; X6.11 79.94,9.7 ; 18.32,54.24 X7.4 ; X7.4 19.37,55.29 ; X7.4 20.42,54.24 ; X7.4 19.37,53.19 ; 10.1,61.8 UNK+3.3V.1 ; UNK+3.3V.1 9,62.9 ; UNK+3.3V.1 11.2,62.9 ; UNK+3.3V.1 10.1,64 ; 87.73,95.87 X5.1 ; X5.1 88.78,94.82 ; X5.1 88.78,96.92 ; X5.1 89.83,95.87
  BOTTOM w0.3: C388.1 v1(75.66,53.04) ; C39.1 80.8,141.35 v2(79.95,141.35) ; C35.1 87.35,117.15 v2(87.35,117.85) ; C196.1 v1(42,79) ; v1(38,84) 38.8,83.2 C119.1 ; v2(53.45,119.7) 53.45,119.15 C34.1 ; C110.1 42.1,99.1 v1(41,98) ; v3(58.25,168.25) 58.35,168.15 C52.1 ; C40.1 71.3,141.8 70.85,141.35 v2(70.45,141.35) ; C31.1 59.25,110.55 v2(59.65,110.95) ; v2(84.55,126.75) 84.15,126.75 C36.1 ; C118.1 v1(18,87) ; v1(15,87) 14.4,87.6 C114.1 ; C33.1 77.95,114.25 v2(77.95,113.65) ; v3(61.8,130.25) R24.1 60.75,130.15 C30.1 v2(57.45,127.75) ; C61.1 81.35,164.25 v2(81.65,164.25) ; C190.1 18.4,90.4 v1(19,91) ; C109.1 14.4,75.4 v1(15,76) 15.6,76.6 17.4,76.6 v1(18,76) C116.1 ; v3(61.15,178.65) 60.85,178.95 C51.1 ; v2(56.85,137.25) 57.55,137.25 C29.1 57.75,140.15 59.6,142 C41.1 61.8,142 v2(62.45,141.35) ; C38.1 v2(84.55,135.25) ; v2(81.65,178.85) C59.1 ; v1(38,94) 38.2,93.8 C117.1 ; C70.1 63.95,90.55 v2(64.55,90.55) ; v2(84.55,127.75) 84.15,127.75 C37.1 ; R9.1 88.25,122.25 v2(88.1,122.1) ; C132.1 19.1,93.9 v1(19,94) ; v1(15,98) 14.9,98.1 C113.1 ; v3(67.25,166.65) 67.65,166.65 C57.1 ; v1(14,84) 14.4,83.6 C115.1 ; C62.1 81.15,159.45 v2(81.65,159.45) ; v1(18,84) 17.8,83.8 C194.1 18.8,82 v1(21,82) ; C60.1 v2(78.85,168.25) ; C120.1 14.4,79.4 v1(15,80) 15.6,80.6 17.4,80.6 v1(18,80) 17.6,79.6 C112.1 ; v3(46.95,161.85) 47.35,161.85 C50.1 ; v3(67.45,161.85) 67.85,161.85 C58.1 ; v1(38,91) 38.2,90.8 C198.1 ; v1(38,79) 38.2,79.2 C131.1 ; C197.1 v1(42,75) ; C64.1 71.48,196.08 v2(71.3,195.9) 71.1,196.1 C65.1 ; 68.55,114.55 68.95,114.15 68.95,114.1 ; C195.1 v1(42,84) ; C49.1 v3(46.95,166.65) ; C32.1 68.95,114.1 ; 68.95,114.1 v2(68.95,113.65) ; v1(38,86) 38.8,85.2 C111.1 ; C63.1 v2(81.65,157.85)
  BOTTOM w0.4: C171.1 R104.1 R105.1 ; R113.1 R112.1 C179.1 ; C151.1 R86.1 R87.1 ; R97.1 R96.1 C163.1
  BOTTOM w0.5: v3(76.2,79.9) 75.22,79.9 74.92,79.6 74.92,79.55 ; v2(56.3,24.5) C173.1 ; R85.2 v3(3.9,30.2) ; 74.92,79.55 C73.1 74.87,79.6 ; 74.92,79.55 74.87,79.55 ; v1(91.51,198.19) 91.95,197.75 C385.1 ; 74.87,79.55 74.87,79.55 74.87,77.43 C74.1 ; 74.87,79.55 74.87,79.55 74.87,79.6 ; C155.1 v2(8.3,24.5) ; R161.1 84.4,191.1 v1(84.3,191.21) 84.19,191.1 C386.1 ; v1(30.7,185.8) 29.9,185 C383.1 ; 74.87,81.25 74.87,82.95 L2.1 74.87,81.25 74.87,81.25 ; 74.87,81.25 74.87,79.6 ; R58.1 81,9.71 X6.11 ; R118.1 R119.1 45.7,135.9 v3(45.3,135.5) ; R146.2 v2(45,84.8) ; C135.1 10.2,154.9 10.7,155.4 v3(11.4,155.4) 11.8,155.4 12.3,154.9 C136.1 ; v1(41.5,102.7) R25.1 R139.1 R42.1 ; v3(24.8,157) 24.8,175.3 23,177.1 R80.1 C133.2 ; v1(37.2,192.41) 36.9,192.71 C382.1 R156.1 ; R67.2 R66.2 v1(11.3,51.7) ; R7.2 R6.2 v3(87.15,65.95) ; v2(40.3,24.6) C165.1 ; R18.1 R19.1 R20.1 R21.1 68.1,61.1 68.7,61.1 v3(69.6,60.2) ; C387.1 v1(91.5,191.25) 91.45,191.2 R163.2 ; C163.1 v2(30.4,19.65) ; C151.1 v2(14.4,19.65) ; R34.2 v3(84.55,84.45) R32.2 v3(84.55,87.05) R31.2 ; C129.1 15.02,117.3 v3(13.4,117.3) C130.1 ; v1(36.89,182.71) 37.4,183.22 C381.1 37.5,184.1 R157.2 ; C138.1 v3(19.9,155.4) ; R41.1 v1(41.5,112) ; C157.1 v2(24.3,24.5) ; C137.1 v3(14.4,155.4) ; v1(84.39,198.19) 84.38,198.2 C384.1 ; R29.2 v3(84.55,92.1) R30.2 ; C48.1 v3(53.77,167.85) ; R103.2 v3(35.85,30.2) ; C171.1 v2(46.4,19.65) ; R65.2 v2(48,106.2) ; R111.2 v3(51.85,30.2) ; R95.2 v3(19.85,30.2) ; R64.2 v3(44.5,167) ; C179.1 v2(62.4,19.65) ; C139.1 v3(23,155.35) ; v1(29.91,195.5) 29.9,195.49 C380.1
  vias: v3(9.4,156.8) v3(9.8,163.6) v3(9.9,161.4) v3(11.35,158) v3(12.95,156.75) v3(14.5,158.05) v3(18.5,156.8) v3(20,158) v3(21.3,156.85) v3(22.8,164) v3(22.8,160.7) v3(22.85,158)
+5VD: length 123.7
  TOP w0.4: D28.2 32,50.1 v1(31.7,50.4) 32.05,50.75 D28.1 ; D28.7 32.05,46.85 v1(31.7,47.2) 32,47.5 D28.6
  TOP w0.5: D18.16 v3(82.72,39.6) 73.1,39.6 59.99,52.71 v4(59.99,63.3)
  TOP w0.8: v4(59.99,66.3) D16.3 v4(59.99,63.3) ; v4(41.86,152.69) D4.3 v4(41.86,149.69)
  VCC w0.55: X1.C2 12.64,210.42 ; X1.C2 13.64,209.42 ; X1.C2 12.64,208.42 ; X1.C2 11.64,209.42 ; X1.B2 12.64,212.96 ; X1.B2 13.64,211.96 ; X1.B2 11.64,211.96 ; X1.B2 12.64,210.96 ; 10.1,213.45 X1.A1 ; X1.A1 9.05,214.5 ; X1.A1 11.15,214.5 ; X1.A1 10.1,215.55 ; X1.B1 11.1,211.96 ; X1.B1 9.1,211.96 ; X1.B1 10.1,212.96 ; X1.B1 10.1,210.96 ; 11.64,214.5 X1.A2 ; X1.A2 13.64,214.5 ; X1.A2 12.64,213.5 ; X1.A2 12.64,215.5 ; X1.C1 11.1,209.42 ; X1.C1 9.1,209.42 ; X1.C1 10.1,208.42 ; X1.C1 10.1,210.42 ; 4.8,74.4 UNK+5V.1 ; UNK+5V.1 3.7,75.5 ; UNK+5V.1 5.9,75.5 ; UNK+5V.1 4.8,76.6
  BOTTOM w0.5: C141.1 59.12,62.44 v4(59.99,63.3) ; C215.2 27.62,50.32 C217.2 29.88,50.4 v1(31.7,50.4) ; v4(59.99,66.3) 59.3,66.3 58.9,65.9 C140.1 ; C182.1 v3(82.72,39.6) 82.75,39.62 C185.1 84.4,41.6 C183.2 ; C134.1 v3(10.9,185.1)
  BOTTOM w1: C42.1 41.86,152.76 v4(41.86,152.69) ; 21.7,146.3 v4(21.1,145.7) ; 21.7,146.3 32.7,146.3 34.25,147.85 C43.1 42.53,149.02 v4(41.86,149.69) ; 21.7,146.3 v4(21.13,146.87)
  vias: v3(11.75,184.15) v3(12.55,185.1) v3(13.1,184.2)
GNDD: length 2470.5
  TOP w0.2: D32.28 v1(91.5,189.3) ; D32.34 v1(91.5,193.11) ; D31.45 38.8,185.41 v1(38.4,185.8) ; D31.15 v1(31.81,196.89) ; D32.21 v1(84.3,189.3) ; D9.R17 v1(28,87) D9.P16 ; v1(27.5,192.6) 28,193.1 D31.21 ; D32.45 v1(91.41,200.09) ; D31.10 34.98,193.09 v1(34.5,192.6) ; D32.39 v1(91.5,196.28) ; D32.4 v1(84.3,200.09) ; D31.34 31.81,185.31 32.6,186.1 34.3,186.1 34.98,185.41 D31.39 v1(34.98,182.81) ; D32.10 v1(84.39,196.28) ; v1(26.9,185.8) 27.7,185.8 28,185.5 D31.28 ; D32.15 v1(84.29,193.11) ; D31.4 v1(38.8,196.9)
  TOP w0.3: v2(79.65,144.15) 79.45,143.95 D1.165 ; D8.29 v2(66.75,85.35) ; D9.AC16 v1(37,86) ; D9.N6 v1(26,76) ; D1.30 v2(56.95,125.75) ; D9.F9 v1(19,80) ; D9.M20 v1(26,90) ; D9.U15 v1(30,85) D9.T14 ; D9.W6 v1(32,76) ; D9.B5 v1(16,76) ; D9.N15 v1(26,85) D9.M14 ; v2(74.5,200.4) 74.4,200.4 74.3,200.5 D7.46 ; D9.U19 v1(30,90) D9.T20 ; v2(71.7,190.9) 71.8,190.9 71.9,191 D7.27 ; D9.M10 v1(26,81) D9.N11 ; R44.2 v3(79.25,88.95) ; D9.F6 v1(19,76) ; D9.K14 v1(24,84) D9.L13 ; D9.L19 v1(24,90) D9.K20 ; D33.3 72.4,51.1 v1(73,50.5) 72.33,49.83 D33.4 ; D1.189 67.45,143.85 v2(67.65,144.05) ; D9.AA27 v1(35,98) ; D5.52 v3(67.45,159.45) ; D8.35 69.75,82.65 70.2,82.2 v2(70.4,82.2) ; D9.R8 v1(28,79) D9.R9 ; v2(67.35,178.65) D5.28 ; D5.12 v2(78.85,166.65) ; D9.AC9 v1(37,79) ; D9.V18 D9.U17 v1(30,87) D9.T16 ; D9.W13 v1(32,83) D9.V12 v1(30.5,83.5) v1(30,83) D9.T12 D9.R11 v1(28,81) D9.P10 ; D6.46 v3(46.95,164.25) ; D9.F16 v1(19,87) ; v2(69.25,110.85) 69.45,111.05 D1.76 ; D9.B13 v1(16,84) ; D9.AF28 v1(40,98) D9.AG27 ; D9.K18 D9.J18 v1(22,88) ; D6.54 v3(46.95,157.85) ; D1.153 87.05,138.75 v2(87.25,138.55) ; v2(62.55,110.85) 62.95,111.25 D1.63 ; D33.7 78.29,52.37 ; 78.29,52.37 78.47,52.37 78.9,52.8 78.9,52.98 ; 78.29,52.37 78.9,52.98 ; D9.N13 v1(26,83) D9.M12 D9.L11 v1(24,81) D9.K10 ; D9.F20 v1(20,91) ; D1.184 69.95,143.85 v2(70.15,144.05) ; D9.AA20 v1(35,90) ; D1.200 61.95,143.85 v2(62.15,144.05) ; D9.AG5 v1(41,75) ; D9.AF1 38.2,70.2 v1(37.1,70.2) ; D5.41 v3(67.25,168.25) ; D9.AC20 v1(37,91) ; v1(22,81) D9.J11 D9.K12 ; D1.147 v2(87.15,135.75) ; v2(54.15,136.95) 54.35,136.75 D1.8 ; D33.1 72.46,53.64 v1(73.1,53) 72.47,52.37 D33.2 ; D1.34 54.45,123.75 v2(54.05,124.15) ; C54.2 v2(64.35,158.65) C55.2 ; D9.AG16 v1(41,86) ; v2(84.35,118.05) 84.45,118.05 84.65,118.25 D1.112 ; D8.17 v2(64.55,89.05) ; C46.2 v2(64.65,168.05) ; D9.AC13 v1(37,84) ; D9.W19 v1(32,90) D9.V20 ; D9.N23 v1(27,93) ; v1(27,93) D9.P22 ; v1(27,93) D9.N22 ; v1(27,93) D9.P23 ; D9.AG9 v1(40,79) ; D9.R15 v1(28,85) D9.P14 ; D9.H9 v1(22,80) ; D9.T6 v1(30,77) ; D9.AC6 v1(36,76) ; D9.N27 v1(27,98) ; D9.V16 v1(32,87) D9.W17 D9.Y18 ; D9.B24 v1(16,94) ; D1.39 v2(56.95,121.25) ; v1(78.96,53.04) 78.9,52.98 ; HL7.2 v3(63.63,69.7) ; R16.1 v3(92.85,119.75) R14.1 ; D1.41 v2(56.95,120.25) ; D9.P20 v1(28,90) D9.R19 ; R47.2 v3(79.25,85.35) ; D9.P18 D9.N17 v1(26,87) D9.M16 ; D9.K23 v1(23,94) ; D9.C28 v1(16,98) D9.B27 ; D9.V10 v1(32,81) D9.W11 D9.Y11 ; D9.P12 v1(28,83) D9.R13 ; D1.130 v2(87.15,127.25) ; v2(87.25,128.05) 87.05,128.25 D1.132 ; D9.AA9 v1(34,79) ; D9.N2 v1(26,72) ; D9.U9 v1(30,79) ; D9.AC23 v1(37,94) ; D9.F13 v1(19,84) ; D9.W9 v1(32,79) ; D9.L9 v1(24,79) ; D6.52 v3(46.95,159.45) ; D9.F23 v1(20,94) ; D9.B9 v1(16,80) ; D1.94 78.45,111.15 v2(78.15,110.85) ; D9.K6 v1(24,77) ; D9.AG24 v1(41,95) ; v2(57.15,127.05) 56.95,127.25 D1.27 ; D9.AG2 v1(40,73) ; D8.45 v2(70.45,89.55) ; D9.V14 v1(32,85) D9.W15 ; D9.L15 v1(24,86) D9.K16 ; D9.W23 v1(32,93) ; D9.B20 v1(16,91) ; D9.N9 v1(26,79) ; D9.AA2 v1(34,73) ; D9.B2 v1(16,72) D9.C1 ; D5.6 v2(81.65,161.85) ; D9.T2 v1(30,73) ; D6.28 v2(46.85,178.65) ; D9.M22 v1(25,93) ; D6.41 v3(46.95,168.25) ; D9.N19 v1(26,89) D9.M18 ; D9.H2 v1(21,73) ; D9.U11 v1(30,81) D9.T10 ; v2(87.35,120.45) 87.05,120.75 D1.117 ; D9.T27 v1(30,98) ; D9.AG13 v1(41,84) ; D1.57 v2(59.95,113.65) ; D9.L17 v1(24,87) ; D9.AG20 v1(41,91) ; D9.T23 v1(29,93) ; D1.20 v2(56.85,130.75) ; D5.46 v2(67.35,164.25) ; D9.T18 D9.R17 ; D9.H27 v1(21,98) ; D9.B16 v1(16,87) ; D9.H20 v1(22,90) ; D5.54 v3(67.45,157.85) ; D8.11 v2(65.25,93.85)
  TOP w0.4: v3(61.15,166.45) 60.95,166.65 D6.12 ; R115.2 v3(21.6,17.6) ; R116.2 v3(37.6,17.6) ; D6.6 v3(61.05,161.85) ; D28.10 40.45,48.15 v1(40.8,48.5) 40.5,48.8 D28.11 ; R51.2 v2(67,80) ; D28.3 v1(31.85,49.45) ; C53.2 v3(64.35,163.4) ; R117.2 v3(53.6,17.6)
  TOP w0.5: R140.1 v1(56.2,87.4) ; HL8.2 v1(27.7,56.7) ; D3.3 81.66,54.21 C4.2 v3(79.7,53.4) ; C219.2 v3(25.7,48.8) ; G1.3 v3(35.65,127.65) ; G1.3 v3(37.95,129.35) ; G1.3 v3(37.95,125.95) ; D11.3 v2(8.95,28.45) ; v3(53.1,65.9) 51.6,67.4 C189.2 C223.2 ; HL6.2 v3(11.4,140.2) ; R131.1 v3(81.8,42.6) ; D2.7 v3(91.65,68.08) 92.12,68.08 C1.2 ; C56.2 v3(66.7,154.45) ; D14.3 v2(56.95,28.45) ; v3(37.85,119.55) G2.3 v3(37.85,123.05) ; R134.2 v3(95,50.5) ; C164.2 v3(47.35,29.95) ; D2.4 v3(82.94,65.54) ; v3(9.2,173.9) CE1.2 v3(9.2,178.75) ; D13.3 v2(40.95,28.45) ; v3(17.05,150.7) CE3.2 v3(17.05,146) ; G4.2 v3(12,112.22) ; v3(24.8,151.85) CE4.2 v3(24.8,148.65) ; v3(8.15,150.6) CE2.2 v3(8.15,145.85) ; v3(83.05,99.25) G3.3 v3(83.05,95.35) ; D2.2 v3(82.95,68.08) ; C72.1 v3(76.1,32.9) ; D12.3 v2(24.95,28.45) ; C172.2 v3(63.35,29.95) ; D2.1 v3(82.95,69.35) ; D18.15 v3(82.7,40.87) ; D2.3 v3(82.95,66.81) ; C156.2 v3(31.35,29.95) ; C154.2 v3(15.35,29.95) ; C79.1 79.9,32.7 v3(79.7,32.9) ; HL5.2 v3(39.5,133.7)
  TOP w0.55: v2(84.45,112.75) 84.45,113.26 ; v2(84.45,112.75) 84.75,112.75 ; v2(84.45,112.75) 84.21,112.75 ; v2(84.45,112.75) 84.45,112.45 ; 44.21,121.25 v3(44.55,121.25) ; v3(44.55,121.25) 44.88,121.25 ; v3(44.55,121.25) 44.55,120.92 ; v3(44.55,121.25) 44.55,121.76 ; v3(37.95,129.35) 39.77,129.35 ; v3(37.95,129.35) 36.13,129.35 ; v3(37.95,129.35) 37.95,129.8 ; v3(94.9,202.4) 95.43,202.4 ; v3(94.9,202.4) 94.9,202.09 ; v3(94.9,202.4) 94.64,202.4 ; v3(94.9,202.4) 94.9,202.66 ; D15.6 23.8,194.3 ; D15.6 11.7,194.3 ; D15.6 17.75,187.7 ; 71.5,54.57 D33.1 69.75,53.64 ; X16.2 45.54,12.4 ; X16.2 46.94,11 ; X16.2 45.54,9.6 ; v1(73.1,53) 73.1,54.57 ; v1(73.1,53) 73.25,53 ; v1(73.1,53) 73.1,51.86 ; 23.8,189.5 v3(22.65,189.5) 22.65,187.7 ; 46.44,149.53 v4(46.44,149.7) 47.6,149.7 ; v2(52.25,168.75) 52.5,168.75 ; v2(52.25,168.75) 52.25,169.1 ; v2(52.25,168.75) 52.25,168.5 ; v2(52.25,168.75) 51.87,168.75 ; 21.2,68 v1(21,68) 21,65.87 ; X16.4 40.12,5.92 ; X16.4 35.72,5.92 ; X16.4 37.92,3.72 ; X16.4 37.92,8.12 ; GND.1 10,68.3 ; GND.1 11.5,66.8 ; GND.1 10,65.3 ; 27.7,50.21 C219.2 27.7,47.39 ; X13.1 50.84,187.6 ; X13.1 49.4,186.16 ; X13.1 47.96,187.6 ; X13.1 49.4,189.04 ; VD1.1 22.66,181.58 ; VD1.1 20.99,179.15 ; VD1.1 24.32,179.15 ; 3.5,24.5 v3(3.85,24.5) ; v3(3.85,24.5) 3.85,24.21 ; v3(3.85,24.5) 3.85,25 ; v3(3.85,24.5) 4.13,24.5 ; v3(59.05,116.35) 59.05,116.59 ; v3(59.05,116.35) 59.05,115.95 ; v3(59.05,116.35) 59.3,116.35 ; v3(59.05,116.35) 58.65,116.35 ; v3(41.65,137.75) 41.87,137.75 ; v3(41.65,137.75) 41.65,138.24 ; v3(41.65,137.75) 41.65,137.53 ; v3(41.65,137.75) 41.3,137.75 ; 65.46,157.85 C55.2 64.35,156.79 ; v3(19.85,24.5) 20.26,24.5 ; v3(19.85,24.5) 19.85,24.94 ; v3(19.85,24.5) 19.62,24.5 ; v3(19.85,24.5) 19.85,24.27 ; v2(50.55,117.95) 50.55,118.31 ; v2(50.55,117.95) 50.07,117.95 ; v2(50.55,117.95) 50.91,117.95 ; v2(50.55,117.95) 50.55,117.58 ; 94.16,67.45 C1.2 92.75,66.16 ; v3(63.35,29.95) 65.27,29.95 ; v3(63.35,29.95) 61.43,29.95 ; v3(63.35,29.95) 63.35,30.19 ; 74.69,32.9 v3(76.1,32.9) ; v3(76.1,32.9) 77.51,32.9 ; v3(76.1,32.9) 76.1,33.09 ; 13.8,132.26 X11.1 ; X11.1 12.36,133.7 ; X11.1 15.24,133.7 ; X11.1 13.8,135.14 ; 45.88,5.92 X16.3 ; X16.3 48.08,3.72 ; X16.3 48.08,8.12 ; X16.3 50.28,5.92 ; 63.63,69.49 v3(63.63,69.7) 62.47,69.7 ; 89.49,31.54 X18.2 92.31,31.54 ; 74.69,31.8 C72.1 77.51,31.8 ; 78.49,31.8 C79.1 81.31,31.8 ; X17.3 66.28,5.92 ; X17.3 61.88,5.92 ; X17.3 64.08,8.12 ; X17.3 64.08,3.72 ; v3(37.85,123.05) 37.85,123.45 ; v3(37.85,123.05) 36.1,123.05 ; v3(37.85,123.05) 39.6,123.05 ; 11.4,138.79 v3(11.4,140.2) 11.17,140.2 ; X6.10 70.57,3.96 ; X6.10 66.21,3.96 ; X6.10 68.39,6.14 ; X6.10 68.39,1.78 ; 24.1,185.49 v3(24.1,185.75) ; v3(24.1,185.75) 24.53,185.75 ; v3(24.1,185.75) 23.84,185.75 ; v3(24.1,185.75) 24.1,186.17 ; 19.72,5.92 X15.4 ; X15.4 21.92,8.12 ; X15.4 21.92,3.72 ; X15.4 24.12,5.92 ; 36.2,50.95 D28.EP 36.2,46.65 ; G4.2 10.4,113.67 ; G4.2 8.55,112.22 ; G4.2 10.4,110.77 ; 78.49,32.9 v3(79.7,32.9) ; v3(79.7,32.9) 79.7,33.09 ; v3(79.7,32.9) 81.31,32.9 ; 45.43,29.95 v3(47.35,29.95) ; v3(47.35,29.95) 47.35,30.19 ; v3(47.35,29.95) 49.27,29.95 ; 17.27,28.77 C154.2 13.43,28.77 ; X14.3 16.08,8.12 ; X14.3 18.28,5.92 ; X14.3 16.08,3.72 ; X14.3 13.88,5.92 ; 61.43,28.77 C172.2 65.27,28.77 ; X3.2 81.86,61.29 ; X3.2 79.04,61.29 ; X3.2 80.45,62.7 ; v3(9.2,173.9) 10.63,173.9 ; v3(9.2,173.9) 9.2,173.62 ; v3(9.2,173.9) 7.77,173.9 ; X4.1 89.25,5.1 ; X4.1 90.75,3.6 ; X4.1 87.75,3.6 ; X4.1 89.25,2.1 ; v3(90.4,216.2) 90.62,216.2 ; v3(90.4,216.2) 90.4,216.77 ; v3(90.4,216.2) 90.4,215.98 ; v3(90.4,216.2) 90.12,216.2 ; X9.1 65.7,41.84 ; X9.1 65.7,38.96 ; X9.1 64.26,40.4 ; X9.1 67.14,40.4 ; 45.43,28.77 C164.2 49.27,28.77 ; v3(51.4,71.3) 51.74,71.3 ; v3(51.4,71.3) 50.94,71.3 ; v3(51.4,71.3) 51.4,70.92 ; v3(51.4,71.3) 51.4,71.64 ; v3(83.05,99.25) 84.34,99.25 ; v3(83.05,99.25) 81.76,99.25 ; v3(83.05,99.25) 83.05,99.4 ; X10.1 55.44,84.6 ; X10.1 54,83.16 ; X10.1 52.56,84.6 ; X10.1 54,86.04 ; 82.7,66.81 v3(82.95,66.81) ; v3(82.95,66.81) 82.95,66.17 ; v3(82.95,66.81) v3(82.95,68.08) 82.7,68.08 ; 59.7,207.59 v3(59.7,207.8) ; v3(59.7,207.8) 60.16,207.8 ; v3(59.7,207.8) 59.7,208.19 ; v3(59.7,207.8) 59.49,207.8 ; 39.5,132.29 v3(39.5,133.7) 39.27,133.7 ; v3(60.25,183.65) 60.61,183.65 ; v3(60.25,183.65) 59.88,183.65 ; v3(60.25,183.65) 60.25,184.13 ; v3(60.25,183.65) 60.25,183.4 ; 80.15,137.92 v3(80.15,138.25) ; v3(80.15,138.25) 80.15,138.7 ; v3(80.15,138.25) 80.55,138.25 ; v3(80.15,138.25) 79.82,138.25 ; 40.7,124.55 G2.5 42.15,123.1 ; X12.1 60.3,152.34 ; X12.1 58.86,150.9 ; X12.1 60.3,149.46 ; X12.1 61.74,150.9 ; 12.85,187.7 v3(12.85,189.5) 11.7,189.5 ; 24.8,148.35 v3(24.8,148.65) 23.4,148.65 ; 35.65,126.47 v3(35.65,127.65) 35.65,128.83 ; v3(9.2,178.75) 9.2,179.03 ; v3(9.2,178.75) 7.77,178.75 ; v3(9.2,178.75) 10.63,178.75 ; 86.2,69.35 D2.1 84.45,70.28 ; 13.54,9.6 X14.2 ; X14.2 13.54,12.4 ; X14.2 14.94,11 ; X14.4 8.12,5.92 ; X14.4 5.92,3.72 ; X14.4 3.72,5.92 ; X14.4 5.92,8.12 ; 66.94,154.45 v3(66.7,154.45) 66.7,156.37 ; 91.32,79.18 X5.14 92.77,80.63 ; v3(36.7,57.9) 36.7,58.05 ; v3(36.7,57.9) 38.35,57.9 ; v3(36.7,57.9) 35.05,57.9 ; v3(36.7,52.9) 38.35,52.9 ; v3(36.7,52.9) 36.7,52.75 ; v3(36.7,52.9) 35.05,52.9 ; 65.46,163.4 v3(64.35,163.4) 64.35,163.19 ; 92.39,50.5 R134.2 93.8,51.79 ; 20.82,56.78 X7.2 19.37,58.23 ; 18.6,100.19 v1(18.6,100.5) ; v1(18.6,100.5) 18.29,100.5 ; v1(18.6,100.5) 18.6,100.91 ; v1(18.6,100.5) 19.04,100.5 ; v3(31.35,29.95) 33.27,29.95 ; v3(31.35,29.95) 29.43,29.95 ; v3(31.35,29.95) 31.35,30.19 ; 47.9,66.29 C223.2 46.84,67.4 ; v3(62.3,32.2) 62.3,32.6 ; v3(62.3,32.2) 62.75,32.2 ; v3(62.3,32.2) 61.99,32.2 ; v3(62.3,32.2) 62.3,31.89 ; 54.34,87.4 R140.1 55.4,86.29 ; 18.4,36.86 X8.1 ; X8.1 19.84,38.3 ; X8.1 16.96,38.3 ; X8.1 18.4,39.74 ; 65.46,164.25 C53.2 64.35,165.31 ; 58.8,39.09 v1(58.8,38.9) 58.47,38.9 ; 46.3,31.88 v3(46.3,32.2) ; v3(46.3,32.2) 46.62,32.2 ; v3(46.3,32.2) 46.3,32.61 ; v3(46.3,32.2) 45.87,32.2 ; X17.2 62.94,11 ; X17.2 61.54,12.4 ; X17.2 61.54,9.6 ; 47.6,152.7 v4(46.44,152.7) 46.44,152.87 ; 77.25,126.4 v3(77.5,126.4) ; v3(77.5,126.4) 77.5,126.72 ; v3(77.5,126.4) 77.5,126.15 ; v3(77.5,126.4) 78.03,126.4 ; v3(12,112.22) 12.25,112.22 ; v3(12,112.22) 12,113.04 ; v3(12,112.22) 12,111.4 ; 36.1,119.55 v3(37.85,119.55) ; v3(37.85,119.55) 39.6,119.55 ; v3(37.85,119.55) 37.85,119.15 ; 18.7,148.35 CE3.2 15.4,148.35 ; 36.13,125.95 v3(37.95,125.95) ; v3(37.95,125.95) 37.95,125.5 ; v3(37.95,125.95) 39.77,125.95 ; 82.95,70.28 v3(82.95,69.35) 82.7,69.35 ; 23.4,150.25 CE4.2 26.2,150.25 ; 19.37,45.17 X7.10 20.82,46.62 ; 29.88,5.92 X15.3 ; X15.3 34.28,5.92 ; X15.3 32.08,8.12 ; X15.3 32.08,3.72 ; 8.15,145.52 v3(8.15,145.85) 9.58,145.85 ; 23.4,151.85 v3(24.8,151.85) ; v3(24.8,151.85) 26.2,151.85 ; v3(24.8,151.85) 24.8,152.15 ; v3(61.8,127.75) 61.8,127.98 ; v3(61.8,127.75) 61.56,127.75 ; v3(61.8,127.75) 61.8,127.42 ; v3(61.8,127.75) 62.32,127.75 ; X6.9 84.58,6.14 ; X6.9 82.4,3.96 ; X6.9 86.76,3.96 ; 11.7,199.8 v3(12.85,199.8) 12.85,200.9 ; 88.8,203.35 v1(88.8,203.6) ; v1(88.8,203.6) 88.8,203.94 ; v1(88.8,203.6) 88.29,203.6 ; v1(88.8,203.6) 89.05,203.6 ; 82.7,65.54 v3(82.94,65.54) ; v3(82.94,65.54) 82.94,64.92 ; v3(82.94,65.54) 82.94,66.16 ; 95,51.79 v3(95,50.5) 95.21,50.5 ; G2.4 42.15,119.7 ; G2.4 43.6,118.25 ; G2.4 40.7,118.25 ; G2.4 42.15,116.8 ; 46.95,157.28 v3(46.95,157.85) 46.72,157.85 ; 29.43,28.77 C156.2 33.27,28.77 ; 15.4,146 v3(17.05,146) ; v3(17.05,146) 18.7,146 ; v3(17.05,146) 17.05,145.7 ; v3(17.05,150.7) 18.7,150.7 ; v3(17.05,150.7) 17.05,151 ; v3(17.05,150.7) 15.4,150.7 ; 13.43,29.95 v3(15.35,29.95) ; v3(15.35,29.95) 15.35,30.19 ; v3(15.35,29.95) 17.27,29.95 ; 83.05,95.1 v3(83.05,95.35) ; v3(83.05,95.35) 81.54,95.35 ; v3(83.05,95.35) 84.56,95.35 ; 67.45,157.28 v3(67.45,157.85) 67.22,157.85 ; 81.8,41.19 v3(81.8,42.6) 81.99,42.6 ; 9.58,150.6 v3(8.15,150.6) 8.15,150.93 ; X15.2 29.54,12.4 ; X15.2 29.54,9.6 ; X15.2 30.94,11 ; 51.72,5.92 X17.4 ; X17.4 53.92,3.72 ; X17.4 56.12,5.92 ; X17.4 53.92,8.12 ; 12.3,150.62 v3(12.3,150.9) ; v3(12.3,150.9) 12.02,150.9 ; v3(12.3,150.9) 12.3,151.46 ; v3(12.3,150.9) 12.59,150.9 ; v3(51.3,84) 51.3,84.39 ; v3(51.3,84) 51.76,84 ; v3(51.3,84) 50.92,84 ; v3(51.3,84) 51.3,83.62 ; 7.77,176.32 CE1.2 10.63,176.32 ; 55.41,63.13 v4(55.41,63.3) 54.25,63.3 ; 38.35,55.4 CE11.2 35.05,55.4 ; 55.41,66.47 v4(55.41,66.3) 54.25,66.3
  TOP w0.8: v4(55.41,66.3) D16.1 v4(55.41,63.3) ; v4(46.44,152.7) D4.1 v4(46.44,149.7) ; v4(17.75,183.65) D15.3 v4(17.75,186.95) ; v4(24.2,179.95) 23.46,179.95 VD1.1 22.66,178.74 23.25,178.15 v4(24.2,178.15)
  TOP w1: v3(36.7,52.9) CE11.2 v3(36.7,57.9)
  GND1 w0.55: 91.32,87.2 X5.8 ; X5.8 91.32,89.3 ; X5.8 90.27,88.25 ; X5.8 92.37,88.25 ; X1.B8 27.88,212.96 ; X1.B8 28.88,211.96 ; X1.B8 26.88,211.96 ; X1.B8 27.88,210.96 ; 32.08,4.12 X15.3 ; X15.3 32.08,7.72 ; X15.3 33.88,5.92 ; X15.3 30.28,5.92 ; X5.6 91.32,91.84 ; X5.6 92.37,90.79 ; X5.6 91.32,89.74 ; X5.6 90.27,90.79 ; 8.9,66.8 GND.1 ; GND.1 10,65.7 ; GND.1 11.1,66.8 ; GND.1 10,67.9 ; X5.10 92.37,85.71 ; X5.10 90.27,85.71 ; X5.10 91.32,86.76 ; X5.10 91.32,84.66 ; 37.92,4.12 X16.4 ; X16.4 39.72,5.92 ; X16.4 37.92,7.72 ; X16.4 36.12,5.92 ; X1.C9 31.42,209.42 ; X1.C9 29.42,209.42 ; X1.C9 30.42,208.42 ; X1.C9 30.42,210.42 ; X1.C20 58.36,210.42 ; X1.C20 59.36,209.42 ; X1.C20 58.36,208.42 ; X1.C20 57.36,209.42 ; 90.9,30.53 X18.2 ; X18.2 91.91,31.54 ; X18.2 89.89,31.54 ; X18.2 90.9,32.55 ; X1.A20 59.36,214.5 ; X1.A20 57.36,214.5 ; X1.A20 58.36,215.5 ; X1.A20 58.36,213.5 ; 90.27,80.63 X5.14 ; X5.14 91.32,79.58 ; X5.14 92.37,80.63 ; X5.14 91.32,81.68 ; X1.C17 51.74,209.42 ; X1.C17 49.74,209.42 ; X1.C17 50.74,210.42 ; X1.C17 50.74,208.42 ; 5.92,4.12 X14.4 ; X14.4 5.92,7.72 ; X14.4 7.72,5.92 ; X14.4 4.12,5.92 ; X13.1 50.34,187.6 ; X13.1 48.46,187.6 ; X13.1 49.4,188.54 ; X13.1 49.4,186.66 ; X9.1 65.7,41.34 ; X9.1 65.7,39.46 ; X9.1 66.64,40.4 ; X9.1 64.76,40.4 ; 83.76,210.96 X1.B30 ; X1.B30 82.76,211.96 ; X1.B30 83.76,212.96 ; X1.B30 84.76,211.96 ; 79.44,61.29 X3.2 ; X3.2 80.45,60.28 ; X3.2 80.45,62.3 ; X3.2 81.46,61.29 ; X1.C30 84.76,209.42 ; X1.C30 83.76,208.42 ; X1.C30 82.76,209.42 ; X1.C30 83.76,210.42 ; G2.5 43.2,124.55 ; G2.5 42.15,125.6 ; G2.5 42.15,123.5 ; G2.5 41.1,124.55 ; 29.54,10 X15.2 ; X15.2 28.54,11 ; X15.2 29.54,12 ; X15.2 30.54,11 ; 62.28,5.92 X17.3 ; X17.3 64.08,7.72 ; X17.3 65.88,5.92 ; X17.3 64.08,4.12 ; X1.C22 64.44,209.42 ; X1.C22 63.44,210.42 ; X1.C22 62.44,209.42 ; X1.C22 63.44,208.42 ; 17.72,210.96 X1.B4 ; X1.B4 18.72,211.96 ; X1.B4 17.72,212.96 ; X1.B4 16.72,211.96 ; 73.6,208.42 X1.C26 ; X1.C26 74.6,209.42 ; X1.C26 73.6,210.42 ; X1.C26 72.6,209.42 ; X1.A21 61.9,214.5 ; X1.A21 60.9,213.5 ; X1.A21 60.9,215.5 ; X1.A21 59.9,214.5 ; X16.2 46.54,11 ; X16.2 45.54,12 ; X16.2 44.54,11 ; X16.2 45.54,10 ; 63.44,210.96 X1.B22 ; X1.B22 64.44,211.96 ; X1.B22 63.44,212.96 ; X1.B22 62.44,211.96 ; X1.B20 58.36,212.96 ; X1.B20 58.36,210.96 ; X1.B20 59.36,211.96 ; X1.B20 57.36,211.96 ; X7.2 20.42,56.78 ; X7.2 18.32,56.78 ; X7.2 19.37,57.83 ; X7.2 19.37,55.73 ; X17.4 53.92,7.72 ; X17.4 52.12,5.92 ; X17.4 55.72,5.92 ; X17.4 53.92,4.12 ; 26.88,209.42 X1.C8 ; X1.C8 28.88,209.42 ; X1.C8 27.88,208.42 ; X1.C8 27.88,210.42 ; X10.1 54.94,84.6 ; X10.1 54,83.66 ; X10.1 54,85.54 ; X10.1 53.06,84.6 ; X5.2 91.32,96.92 ; X5.2 91.32,94.82 ; X5.2 90.27,95.87 ; X5.2 92.37,95.87 ; G2.4 42.15,119.3 ; G2.4 42.15,117.2 ; G2.4 41.1,118.25 ; G2.4 43.2,118.25 ; X6.9 84.58,5.74 ; X6.9 82.8,3.96 ; X6.9 84.58,2.18 ; X6.9 86.36,3.96 ; 91.32,92.28 X5.4 ; X5.4 90.27,93.33 ; X5.4 91.32,94.38 ; X5.4 92.37,93.33 ; 60.3,149.96 X12.1 ; X12.1 59.36,150.9 ; X12.1 61.24,150.9 ; X12.1 60.3,151.84 ; X15.4 21.92,7.72 ; X15.4 23.72,5.92 ; X15.4 21.92,4.12 ; X15.4 20.12,5.92 ; 17.46,38.3 X8.1 ; X8.1 18.4,37.36 ; X8.1 19.34,38.3 ; X8.1 18.4,39.24 ; X6.10 70.17,3.96 ; X6.10 66.61,3.96 ; X6.10 68.39,2.18 ; X6.10 68.39,5.74 ; 46.28,5.92 X16.3 ; X16.3 48.08,7.72 ; X16.3 48.08,4.12 ; X16.3 49.88,5.92 ; 14.28,5.92 X14.3 ; X14.3 16.08,4.12 ; X14.3 16.08,7.72 ; X14.3 17.88,5.92 ; X1.A30 83.76,215.5 ; X1.A30 82.76,214.5 ; X1.A30 84.76,214.5 ; X1.A30 83.76,213.5 ; 89.25,2.5 X4.1 ; X4.1 90.35,3.6 ; X4.1 88.15,3.6 ; X4.1 89.25,4.7 ; 60.54,11 X17.2 ; X17.2 61.54,12 ; X17.2 62.54,11 ; X17.2 61.54,10 ; X7.10 20.42,46.62 ; X7.10 19.37,45.57 ; X7.10 18.32,46.62 ; X7.10 19.37,47.67 ; 13.8,132.76 X11.1 ; X11.1 12.86,133.7 ; X11.1 14.74,133.7 ; X11.1 13.8,134.64 ; 72.6,211.96 X1.B26 ; X1.B26 74.6,211.96 ; X1.B26 73.6,210.96 ; X1.B26 73.6,212.96 ; 59.9,211.96 X1.B21 ; X1.B21 61.9,211.96 ; X1.B21 60.9,212.96 ; X1.B21 60.9,210.96 ; X1.C21 61.9,209.42 ; X1.C21 60.9,208.42 ; X1.C21 59.9,209.42 ; X1.C21 60.9,210.42 ; X14.2 13.54,12 ; X14.2 13.54,10 ; X14.2 12.54,11 ; X14.2 14.54,11 ; X1.C6 23.8,209.42 ; X1.C6 22.8,210.42 ; X1.C6 22.8,208.42 ; X1.C6 21.8,209.42
  MIDLAYER w0.15: v1(33.5,70.2) 33.5,48 34.7,46.8 v3(35,46.8) 35,46.3 42.2,39.1 v1(42.7,39.1) ; v1(16,72) 15.4,71.4 15.4,70.8 15.9,70.3 15.9,65.6 9.4,59.1 9.4,39.5 v1(9,39.1) ; v1(26.8,39.2) 26.4,39.6 26.4,40.5 24.2,42.7 24.2,63 21,66.2 v1(21,68) ; v1(57.1,39) 57.4,39.3 57.4,54 45.5,65.9 35.76,65.9 35.3,66.36 35.3,67.5 35.5,67.7 v1(35.5,70.2) ; v1(11,39) 10.9,39 10.6,39.3 10.6,58.5 17.5,65.4 17.5,66.8 18,67.3 v1(18,68) ; v1(25,39.1) 25,39.9 22.9,42 22.9,62 19.3,65.6 19.3,67.9 v1(19.4,68) ; v1(58.8,38.9) 58.5,39.2 58.5,54.7 45.9,67.3 37.6,67.3 37.1,67.8 v1(37.1,70.2) ; v1(31.7,70) 31.7,62.8 32.3,62.2 32.3,47.3 40.4,39.2 v1(40.4,39)
  MIDLAYER w0.55: 92.67,95.87 X5.2 91.32,97.22 ; X13.1 50.64,187.6 ; X13.1 48.16,187.6 ; X13.1 49.4,186.36 ; X13.1 49.4,188.84 ; X14.2 13.54,12.3 ; X14.2 13.54,9.7 ; X14.2 14.84,11 ; X4.1 89.25,5 ; X4.1 90.65,3.6 ; X4.1 87.85,3.6 ; X4.1 89.25,2.2 ; 92.67,80.63 X5.14 91.32,79.28 ; 10,65.4 GND.1 ; GND.1 8.6,66.8 ; GND.1 11.4,66.8 ; GND.1 10,68.2 ; X17.3 64.08,8.02 ; X17.3 66.18,5.92 ; X17.3 64.08,3.82 ; X17.3 61.98,5.92 ; X6.10 70.47,3.96 ; X6.10 68.39,1.88 ; X6.10 68.39,6.04 ; X6.10 66.31,3.96 ; 29.98,5.92 X15.3 ; X15.3 34.18,5.92 ; X15.3 32.08,3.82 ; X15.3 32.08,8.02 ; 40.8,124.55 G2.5 ; G2.5 42.15,123.2 ; G2.5 42.15,125.9 ; G2.5 43.5,124.55 ; X16.2 45.54,12.3 ; X16.2 45.54,9.7 ; X16.2 46.84,11 ; X8.1 18.4,39.54 ; X8.1 17.16,38.3 ; X8.1 18.4,37.06 ; X8.1 19.64,38.3 ; X3.2 80.45,62.6 ; X3.2 81.76,61.29 ; X3.2 79.14,61.29 ; X15.2 29.54,12.3 ; X15.2 29.54,9.7 ; X15.2 30.84,11 ; 40.8,118.25 G2.4 ; G2.4 42.15,116.9 ; G2.4 43.5,118.25 ; G2.4 42.15,119.6 ; 3.82,5.92 X14.4 ; X14.4 5.92,8.02 ; X14.4 8.02,5.92 ; X14.4 5.92,3.82 ; 45.98,5.92 X16.3 ; X16.3 50.18,5.92 ; X16.3 48.08,8.02 ; X16.3 48.08,3.82 ; 12.56,133.7 X11.1 ; X11.1 15.04,133.7 ; X11.1 13.8,132.46 ; X11.1 13.8,134.94 ; X16.4 40.02,5.92 ; X16.4 35.82,5.92 ; X16.4 37.92,3.82 ; X16.4 37.92,8.02 ; 60.3,149.66 X12.1 ; X12.1 60.3,152.14 ; X12.1 61.54,150.9 ; X12.1 59.06,150.9 ; 19.37,58.13 X7.2 20.72,56.78 ; X17.4 53.92,8.02 ; X17.4 51.82,5.92 ; X17.4 56.02,5.92 ; X17.4 53.92,3.82 ; X9.1 65.7,41.64 ; X9.1 66.94,40.4 ; X9.1 64.46,40.4 ; X9.1 65.7,39.16 ; 20.72,46.62 X7.10 19.37,45.27 ; 21.92,3.82 X15.4 ; X15.4 19.82,5.92 ; X15.4 24.02,5.92 ; X15.4 21.92,8.02 ; 61.54,9.7 X17.2 ; X17.2 61.54,12.3 ; X17.2 62.84,11 ; X6.9 84.58,6.04 ; X6.9 84.58,1.88 ; X6.9 82.5,3.96 ; X6.9 86.66,3.96 ; 13.98,5.92 X14.3 ; X14.3 16.08,3.82 ; X14.3 18.18,5.92 ; X14.3 16.08,8.02 ; X10.1 55.24,84.6 ; X10.1 52.76,84.6 ; X10.1 54,85.84 ; 92.21,31.54 X18.2 89.59,31.54
  GND2 w0.55: 90.27,88.25 X5.8 ; X5.8 91.32,87.2 ; X5.8 91.32,89.3 ; X5.8 92.37,88.25 ; 28.54,11 X15.2 ; X15.2 30.54,11 ; X15.2 29.54,10 ; X15.2 29.54,12 ; 72.6,209.42 X1.C26 ; X1.C26 73.6,208.42 ; X1.C26 74.6,209.42 ; X1.C26 73.6,210.42 ; X1.C30 83.76,210.42 ; X1.C30 82.76,209.42 ; X1.C30 84.76,209.42 ; X1.C30 83.76,208.42 ; 59.9,211.96 X1.B21 ; X1.B21 61.9,211.96 ; X1.B21 60.9,210.96 ; X1.B21 60.9,212.96 ; 26.88,211.96 X1.B8 ; X1.B8 28.88,211.96 ; X1.B8 27.88,212.96 ; X1.B8 27.88,210.96 ; 62.44,211.96 X1.B22 ; X1.B22 64.44,211.96 ; X1.B22 63.44,212.96 ; X1.B22 63.44,210.96 ; 59.9,209.42 X1.C21 ; X1.C21 61.9,209.42 ; X1.C21 60.9,208.42 ; X1.C21 60.9,210.42 ; 45.54,10 X16.2 ; X16.2 44.54,11 ; X16.2 46.54,11 ; X16.2 45.54,12 ; X4.1 89.25,4.7 ; X4.1 88.15,3.6 ; X4.1 90.35,3.6 ; X4.1 89.25,2.5 ; 91.32,94.82 X5.2 ; X5.2 91.32,96.92 ; X5.2 92.37,95.87 ; X5.2 90.27,95.87 ; X1.C9 31.42,209.42 ; X1.C9 30.42,208.42 ; X1.C9 29.42,209.42 ; X1.C9 30.42,210.42 ; 16.72,211.96 X1.B4 ; X1.B4 18.72,211.96 ; X1.B4 17.72,210.96 ; X1.B4 17.72,212.96 ; 84.58,2.18 X6.9 ; X6.9 84.58,5.74 ; X6.9 82.8,3.96 ; X6.9 86.36,3.96 ; X5.6 91.32,91.84 ; X5.6 90.27,90.79 ; X5.6 92.37,90.79 ; X5.6 91.32,89.74 ; X1.A30 84.76,214.5 ; X1.A30 83.76,215.5 ; X1.A30 82.76,214.5 ; X1.A30 83.76,213.5 ; X15.3 33.88,5.92 ; X15.3 32.08,4.12 ; X15.3 30.28,5.92 ; X15.3 32.08,7.72 ; 36.12,5.92 X16.4 ; X16.4 39.72,5.92 ; X16.4 37.92,4.12 ; X16.4 37.92,7.72 ; 64.76,40.4 X9.1 ; X9.1 66.64,40.4 ; X9.1 65.7,41.34 ; X9.1 65.7,39.46 ; X11.1 13.8,134.64 ; X11.1 12.86,133.7 ; X11.1 14.74,133.7 ; X11.1 13.8,132.76 ; 91.32,79.58 X5.14 ; X5.14 91.32,81.68 ; X5.14 92.37,80.63 ; X5.14 90.27,80.63 ; 58.36,210.96 X1.B20 ; X1.B20 59.36,211.96 ; X1.B20 57.36,211.96 ; X1.B20 58.36,212.96 ; 60.54,11 X17.2 ; X17.2 61.54,12 ; X17.2 62.54,11 ; X17.2 61.54,10 ; 18.32,56.78 X7.2 ; X7.2 20.42,56.78 ; X7.2 19.37,57.83 ; X7.2 19.37,55.73 ; 72.6,211.96 X1.B26 ; X1.B26 73.6,210.96 ; X1.B26 73.6,212.96 ; X1.B26 74.6,211.96 ; X18.2 90.9,32.55 ; X18.2 91.91,31.54 ; X18.2 89.89,31.54 ; X18.2 90.9,30.53 ; X7.10 19.37,47.67 ; X7.10 18.32,46.62 ; X7.10 20.42,46.62 ; X7.10 19.37,45.57 ; X15.4 21.92,7.72 ; X15.4 20.12,5.92 ; X15.4 21.92,4.12 ; X15.4 23.72,5.92 ; X17.3 65.88,5.92 ; X17.3 64.08,4.12 ; X17.3 64.08,7.72 ; X17.3 62.28,5.92 ; 90.27,85.71 X5.10 ; X5.10 91.32,84.66 ; X5.10 91.32,86.76 ; X5.10 92.37,85.71 ; X3.2 81.46,61.29 ; X3.2 79.44,61.29 ; X3.2 80.45,60.28 ; X3.2 80.45,62.3 ; 14.28,5.92 X14.3 ; X14.3 16.08,7.72 ; X14.3 17.88,5.92 ; X14.3 16.08,4.12 ; 17.46,38.3 X8.1 ; X8.1 19.34,38.3 ; X8.1 18.4,39.24 ; X8.1 18.4,37.36 ; 41.1,124.55 G2.5 ; G2.5 42.15,123.5 ; G2.5 42.15,125.6 ; G2.5 43.2,124.55 ; X1.A21 61.9,214.5 ; X1.A21 60.9,213.5 ; X1.A21 60.9,215.5 ; X1.A21 59.9,214.5 ; X1.B30 83.76,212.96 ; X1.B30 82.76,211.96 ; X1.B30 84.76,211.96 ; X1.B30 83.76,210.96 ; X1.C20 58.36,210.42 ; X1.C20 58.36,208.42 ; X1.C20 59.36,209.42 ; X1.C20 57.36,209.42 ; X13.1 49.4,188.54 ; X13.1 48.46,187.6 ; X13.1 49.4,186.66 ; X13.1 50.34,187.6 ; X14.4 7.72,5.92 ; X14.4 5.92,4.12 ; X14.4 4.12,5.92 ; X14.4 5.92,7.72 ; X10.1 54.94,84.6 ; X10.1 54,85.54 ; X10.1 53.06,84.6 ; X10.1 54,83.66 ; X17.4 53.92,7.72 ; X17.4 53.92,4.12 ; X17.4 52.12,5.92 ; X17.4 55.72,5.92 ; X1.C22 64.44,209.42 ; X1.C22 63.44,210.42 ; X1.C22 62.44,209.42 ; X1.C22 63.44,208.42 ; 91.32,92.28 X5.4 ; X5.4 90.27,93.33 ; X5.4 92.37,93.33 ; X5.4 91.32,94.38 ; G2.4 42.15,119.3 ; G2.4 41.1,118.25 ; G2.4 42.15,117.2 ; G2.4 43.2,118.25 ; 48.08,4.12 X16.3 ; X16.3 48.08,7.72 ; X16.3 46.28,5.92 ; X16.3 49.88,5.92 ; X14.2 13.54,12 ; X14.2 14.54,11 ; X14.2 13.54,10 ; X14.2 12.54,11 ; 21.8,209.42 X1.C6 ; X1.C6 22.8,208.42 ; X1.C6 22.8,210.42 ; X1.C6 23.8,209.42 ; X6.10 68.39,5.74 ; X6.10 68.39,2.18 ; X6.10 66.61,3.96 ; X6.10 70.17,3.96 ; 59.36,150.9 X12.1 ; X12.1 60.3,151.84 ; X12.1 61.24,150.9 ; X12.1 60.3,149.96 ; X1.C8 27.88,210.42 ; X1.C8 27.88,208.42 ; X1.C8 26.88,209.42 ; X1.C8 28.88,209.42 ; 57.36,214.5 X1.A20 ; X1.A20 58.36,215.5 ; X1.A20 59.36,214.5 ; X1.A20 58.36,213.5 ; 49.74,209.42 X1.C17 ; X1.C17 50.74,208.42 ; X1.C17 51.74,209.42 ; X1.C17 50.74,210.42 ; 8.9,66.8 GND.1 ; GND.1 10,65.7 ; GND.1 11.1,66.8 ; GND.1 10,67.9
  BOTTOM w0.15: v1(34,73) 33.2,72.2 33.2,70.5 v1(33.5,70.2) v1(35.5,70.2) ; C204.2 v1(21,68)
  BOTTOM w0.3: 48.77,116.17 48.77,116.17 47.75,116.17 ; v3(46.95,164.25) 47.35,164.25 C50.2 ; C57.2 67.65,164.25 v2(67.35,164.25) ; C222.2 22.8,100.7 v1(22.5,100.4) ; v1(26,83) 25.9,82.9 C98.2 ; C49.2 v3(46.95,168.25) ; C188.2 v1(18.6,100.5) ; v1(37,91) 36.6,90.6 C198.2 ; C127.2 30.7,77 v1(30,77) ; C128.2 32.7,76.7 v1(32,76) ; v2(81.85,154.65) 81.65,154.85 C63.2 ; 85.45,112.75 85.25,112.75 ; 85.25,112.75 v2(84.45,112.75) ; 85.25,112.75 R10.1 ; v1(32,93) 32.8,93 C201.2 C212.2 ; C114.2 v1(16,87) ; C111.2 37,85.2 v1(37,86) ; v1(26,79) 26.2,79 C88.2 ; C109.2 v1(16,76) ; C99.2 28.6,90 v1(28,90) 27.4,90 C102.2 26.6,90 v1(26,90) 25.4,90 C106.2 24.6,90 v1(24,90) 23.4,90 C91.2 ; C100.2 31.4,90 v1(32,90) 32.6,90 C89.2 ; v1(19,84) 19.4,83.6 C194.2 ; C62.2 81.65,161.55 v2(81.65,161.85) 81.35,161.85 C61.2 ; v1(37,84) 37.2,83.8 C119.2 ; C103.2 23.9,79 v1(24,79) 24.1,79 C107.2 ; C90.2 v1(24,86) ; v2(79.65,144.15) 80.9,144.15 C39.2 ; C205.2 C126.2 20.8,72.8 v1(21,73) ; v1(40,98) 40.5,98.5 C110.2 ; C104.2 23.7,81.3 v1(24,81) ; C58.2 67.85,159.45 v3(67.45,159.45) ; v2(78.85,166.65) C60.2 ; C94.2 31.4,84.4 v1(32,85) 32.6,84.4 C105.2 C87.2 ; C125.2 16.1,72.1 v1(16,72) 15.9,72.1 C203.2 ; v2(84.35,118.05) 84.35,117.05 C35.2 ; R82.2 v3(21.15,191.65) ; v1(28,79) C191.2 C192.2 C193.2 ; v1(20,94) 20.7,93.3 C132.2 ; v1(25,93) 24.8,92.8 C202.2 C208.2 23,92.9 v1(23,94) ; C116.2 19.6,75.4 v1(19,76) ; v2(70.15,144.05) 70.15,144.45 70.6,144.9 C40.2 ; v1(34,73) 34.2,73.2 C211.2 C206.2 C213.2 C123.2 39.8,73.2 v1(40,73) 40.2,73.2 C214.2 ; v1(37,94) 36.6,93.6 C117.2 ; v1(30,73) 30.2,73.2 C124.2 ; C195.2 40.4,83.4 v1(41,84) ; C24.2 67.5,144.2 v2(67.65,144.05) ; C92.2 27.9,82.9 v1(28,83) ; C96.2 29.8,82.8 v1(30,83) ; C120.2 v1(16,80) ; v1(26,76) 25.5,76.5 C207.2 24.5,76.5 v1(24,77) D9.K6 C121.2 ; v1(34,79) 34.6,79.6 C210.2 ; v1(26,85) 25.4,84.4 C97.2 ; C118.2 19.6,86.4 v1(19,87) ; v1(22,80) 21.4,80 C122.2 ; C112.2 19.2,79.8 v1(19,80) ; C204.2 v1(19.4,68) C200.2 v1(18,68) ; C51.2 57.15,178.95 v2(56.85,178.65) ; v2(62.15,144.05) 61.8,144.4 C41.2 ; v3(92.85,119.75) 92.85,121.55 92.15,122.25 C2.2 ; C115.2 v1(16,84) ; C52.2 v2(61.45,168.15) ; C10.1 50.85,117.65 v2(50.55,117.95) 50.55,118.65 C34.2 ; C65.2 v2(70.5,198.4) ; C101.2 27.4,84.4 v1(28,85) ; C93.2 31.8,82.8 v1(32,83) 32.2,82.8 C108.2 ; v1(16,98) D9.C28 C113.2 ; C190.2 v1(20,91) ; v1(37,79) 36.6,79.4 C131.2 ; C388.2 v1(78.96,53.04) ; C199.2 v1(36,76) ; C95.2 29.4,84.4 v1(30,85) ; C36.2 v3(81.25,127.25) C37.2 ; C59.2 79.35,179.45 v2(78.65,178.75) ; R79.2 v3(24.1,185.75) ; v2(64.55,89.05) C70.2 ; C196.2 40.4,79.4 v1(40,79) ; C209.2 25.6,73.4 v1(26,73) ; v1(41,75) 40.4,75.6 C197.2
  BOTTOM w0.4: v2(67,80) 67,80.5 66.55,80.95 C81.2 ; C151.2 v2(14.4,22.05) ; C179.2 v2(62.4,22.05) ; C163.2 v2(30.4,22.05) ; C171.2 v2(46.4,22.05)
  BOTTOM w0.5: v1(26.9,185.8) 27.5,185.2 C383.2 ; 58.87,113.35 59.17,113.65 59.17,113.65 ; v3(86.35,59.35) C9.2 C3.2 v3(88.35,59.35) ; v2(65.25,93.85) 65.69,94.29 65.69,94.31 C82.2 ; 59.17,113.65 C22.2 ; 59.17,113.65 v2(59.95,113.65) ; C83.2 C84.2 v3(71.45,93.55) ; C381.2 35,182.83 v1(34.98,182.81) ; C5.1 v3(50.85,126.55) C18.1 ; v1(91.5,189.3) 91.95,188.85 C387.2 ; C85.2 75.5,16.4 v3(75.6,16.3) ; C176.2 v3(62.3,32.2) ; v2(45.95,116.17) 45.95,116.17 C20.2 ; v2(45.95,116.17) 45.47,116.17 C21.2 ; v2(45.95,116.17) 47.75,116.17 ; C136.2 v3(12.3,150.9) ; C78.1 v3(82.4,35.4) ; v1(91.5,196.28) 91.5,195.8 91.95,195.35 C385.2 ; C14.2 v3(44.55,121.25) C17.1 ; C38.2 v3(80.2,135.25) ; C137.2 v3(14.4,150.9) ; C216.1 34.2,59.9 v1(34.2,58.8) ; C165.2 v3(35.85,24.6) ; C142.2 v3(51.4,71.3) ; v3(63.95,83.75) C80.2 65.23,83.75 ; C148.2 v3(14.3,32.2) ; R3.2 v1(88.8,203.6) ; C160.2 v3(30.3,32.2) ; v1(84.3,189.3) 83.7,188.7 C386.2 ; 81.25,138.25 C28.2 v3(80.15,138.25) ; C25.2 50.35,131.55 v3(50.35,131.05) 50.35,130.55 C19.1 ; v3(78.25,118) C33.2 ; C130.2 v3(12.2,120.8) ; 46.45,131.45 C8.2 v3(46.45,132.35) ; C86.2 v3(72.85,13.9) R54.1 v3(70.6,13.9) R53.2 ; R114.2 v3(7.5,17.6) ; C141.2 56.08,62.64 v4(55.41,63.3) ; R28.1 v3(69.5,116.95) C32.2 ; C182.2 v3(79.1,40.8) ; C27.2 81.1,120.3 v3(80.1,120.3) ; C138.2 v3(19.9,150) ; C64.2 74.22,199.12 74.5,199.4 v2(74.5,200.4) ; v4(55.41,66.3) 55.9,66.3 56.5,65.7 C140.2 ; C7.1 50.85,121.35 v3(51.45,121.95) 50.85,122.55 C6.1 ; C16.1 63.05,118.35 v3(62.15,117.45) C26.2 ; C134.2 v3(9.7,188.55) ; C23.2 v3(59.05,116.35) ; 47.75,116.17 47.75,116.17 v2(49.2,116.17) ; 47.75,116.17 47.75,116.17 ; C157.2 v3(19.85,24.5) ; C217.1 27.02,47.28 C215.1 26,47.3 25.7,47.6 v3(25.7,48.8) ; C44.2 v3(41.65,137.75) ; R68.2 v1(11.2,56.8) ; C73.2 71.83,78.77 v3(72.75,77.85) 73.45,77.15 C74.2 ; C15.1 v3(63.05,121.95) C13.1 v3(63.05,124.25) C11.1 ; C139.2 v3(23,150) ; v1(84.39,196.28) 83.9,195.8 C384.2 ; v1(31.7,70) 30.9,69.2 C186.2 ; v1(91,208.4) R2.2 R1.2 ; C30.2 v3(61.8,127.75) ; C69.2 v3(79.65,92.35) ; R133.1 v3(82.7,49.6) ; C173.2 v3(51.85,24.5) ; v3(10.4,150.9) 10.4,151.8 C135.2 ; C47.2 v2(52.25,168.75) ; 41.35,131.45 C12.1 v3(41.35,132.35) ; C71.1 v3(72.3,36.5) ; C155.2 v3(3.85,24.5) ; C129.2 v3(15.1,121.6) ; v3(55.3,110.55) C31.2 ; C75.2 73.15,88.07 C76.2 C77.2 73.15,90.95 v3(73.45,91.25) ; C380.2 v1(27.5,192.6) ; C382.2 v1(34.5,192.6) ; R120.2 30.1,100.4 v1(29.8,100.1) ; C143.2 v3(53.1,65.9) ; C48.2 v3(50.73,167.9) ; C168.2 v3(46.3,32.2) ; v3(61.25,137.45) C29.2 ; C185.2 v3(86.08,36.58) ; C68.2 v3(74.55,92.35) ; C184.2 v3(87.1,49.5) ; C220.2 v2(44.99,86.2) ; C187.2 v1(26.5,69) ; C218.1 v1(40,58.3) ; C45.2 v3(45.15,136.9)
  BOTTOM w0.55: C42.2 46.59,153.8 ; C42.2 45.3,155.21 ; C42.2 45.3,152.39 ; 90.12,216.2 v3(90.4,216.2) ; v3(90.4,216.2) 90.4,216.77 ; v3(90.4,216.2) 90.4,215.98 ; v3(90.4,216.2) 90.62,216.2 ; 61.44,137.45 v3(61.25,137.45) 61.25,138.86 ; 76.84,118 v3(78.25,118) ; v3(78.25,118) 79.66,118 ; v3(78.25,118) 78.25,118.24 ; 56.5,63.69 C140.2 55.21,65.1 ; 35.49,90 C198.2 36.6,88.94 ; 20.82,56.78 X7.2 19.37,58.23 ; 14.3,30.91 v3(14.3,32.2) 14.51,32.2 ; 35.85,23.19 v3(35.85,24.6) ; v3(35.85,24.6) 35.61,24.6 ; v3(35.85,24.6) 35.85,26.01 ; 56.95,28.1 v2(56.95,28.45) ; v2(56.95,28.45) 56.95,28.75 ; v2(56.95,28.45) 57.25,28.45 ; v2(56.95,28.45) 56.45,28.45 ; 44.79,86.2 v2(44.99,86.2) 44.99,87.26 ; 95,50.1 v3(95,50.5) ; v3(95,50.5) 95.45,50.5 ; v3(95,50.5) 95,50.88 ; v3(95,50.5) 94.62,50.5 ; X14.4 8.12,5.92 ; X14.4 5.92,3.72 ; X14.4 5.92,8.12 ; X14.4 3.72,5.92 ; 16.5,100.26 C113.2 17.61,99.2 ; 12.31,188.55 C134.2 10.9,189.84 ; v3(3.85,24.5) 3.85,25.91 ; v3(3.85,24.5) 3.61,24.5 ; v3(3.85,24.5) 3.85,23.09 ; v4(17.75,183.65) 17.75,184.06 ; v4(17.75,183.65) 17.75,183.35 ; v4(17.75,183.65) 18.19,183.65 ; v4(17.75,183.65) 17.45,183.65 ; 44.55,123.96 C14.2 43.26,122.55 ; v3(21.15,191.65) 22.56,191.65 ; v3(21.15,191.65) 21.15,191.89 ; v3(21.15,191.65) 19.74,191.65 ; 47.86,131.5 C8.2 45.04,131.5 ; 82.71,155.45 C63.2 80.59,155.45 ; 64.83,95.37 C82.2 68.67,95.37 ; 40.7,124.55 G2.5 ; G2.5 42.15,126 ; G2.5 42.15,123.1 ; G2.5 43.6,124.55 ; 86.08,35.16 v3(86.08,36.58) 86.32,36.58 ; 39.94,132.35 v3(41.35,132.35) ; v3(41.35,132.35) 42.76,132.35 ; v3(41.35,132.35) 41.35,132.79 ; 62.51,32.2 v3(62.3,32.2) 62.3,30.91 ; 75.96,93.35 C68.2 73.14,93.35 ; 54.15,137.24 v2(54.15,136.95) 54.44,136.95 ; 58.47,38.9 v1(58.8,38.9) 58.8,39.09 ; v3(80.1,120.3) 80.1,121.66 ; v3(80.1,120.3) 80.1,118.84 ; v3(80.1,120.3) 79.86,120.3 ; 62.15,145.69 v2(62.15,144.05) 62.41,144.05 ; v3(19.85,24.5) 19.85,25.91 ; v3(19.85,24.5) 19.61,24.5 ; v3(19.85,24.5) 19.85,23.09 ; 89.25,2.1 X4.1 ; X4.1 87.75,3.6 ; X4.1 90.75,3.6 ; X4.1 89.25,5.1 ; 46.51,32.2 v3(46.3,32.2) 46.3,30.91 ; v3(37.85,123.05) 37.85,123.37 ; v3(37.85,123.05) 37.35,123.05 ; v3(37.85,123.05) 38.17,123.05 ; v3(37.85,123.05) 37.85,122.7 ; 40.24,137.75 v3(41.65,137.75) ; v3(41.65,137.75) 41.65,137.46 ; v3(41.65,137.75) 43.06,137.75 ; v2(40.3,26.45) 40.3,26.72 ; v2(40.3,26.45) 40.58,26.45 ; v2(40.3,26.45) 40.03,26.45 ; v2(40.3,26.45) 40.3,26.01 ; 34.1,58.71 C216.1 ; C216.1 35.51,60 ; C216.1 32.69,60 ; 79.96,126.25 C36.2 81.25,124.84 ; 70.5,198.81 v2(70.5,198.4) 69.44,198.4 ; 77.81,40.8 v3(79.1,40.8) 79.1,41.01 ; 35.65,127.29 v3(35.65,127.65) ; v3(35.65,127.65) 35.27,127.65 ; v3(35.65,127.65) 35.65,128.12 ; v3(35.65,127.65) 36.01,127.65 ; 21.16,68 v1(21,68) 21,66.89 ; 74.55,92.06 v3(74.55,92.35) ; v3(74.55,92.35) 75.96,92.35 ; v3(74.55,92.35) 73.14,92.35 ; 78.96,54.1 v1(78.96,53.04) 79.31,53.04 ; v3(17.05,150.7) 17.31,150.7 ; v3(17.05,150.7) 16.63,150.7 ; v3(17.05,150.7) 17.05,150.96 ; v3(17.05,150.7) 17.05,150.27 ; 67.19,159.85 C58.2 ; C58.2 68.25,158.74 ; C58.2 69.31,159.85 ; 66.21,3.96 X6.10 ; X6.10 70.57,3.96 ; X6.10 68.39,6.14 ; X6.10 68.39,1.78 ; v3(12.85,199.8) 13.12,199.8 ; v3(12.85,199.8) 12.85,199.53 ; v3(12.85,199.8) 12.85,200.13 ; v3(12.85,199.8) 12.33,199.8 ; v2(42.25,28.45) 42.83,28.45 ; v2(42.25,28.45) 42.25,28.67 ; v2(42.25,28.45) 42.03,28.45 ; v2(42.25,28.45) 42.25,28.18 ; 60.25,183.29 v3(60.25,183.65) ; v3(60.25,183.65) 59.88,183.65 ; v3(60.25,183.65) 60.25,184.13 ; v3(60.25,183.65) 60.61,183.65 ; 9.04,27.45 v2(9.28,27.45) ; v2(9.28,27.45) 9.63,27.45 ; v2(9.28,27.45) 9.28,27.21 ; v2(9.28,27.45) 9.28,27.94 ; v3(37.85,119.55) 38.09,119.55 ; v3(37.85,119.55) 37.85,119.98 ; v3(37.85,119.55) 37.43,119.55 ; v3(37.85,119.55) 37.85,119.31 ; X8.1 19.84,38.3 ; X8.1 16.96,38.3 ; X8.1 18.4,36.86 ; X8.1 18.4,39.74 ; 36.13,79 v1(34,79) 34,81.13 ; 92.75,187.56 C387.2 94.16,188.85 ; 4.9,23.09 C155.2 4.9,25.91 ; v2(87.15,135.75) 87.38,135.75 ; v2(87.15,135.75) 87.15,135.52 ; v2(87.15,135.75) 87.15,136.01 ; v2(87.15,135.75) 86.56,135.75 ; 40,57.96 v1(40,58.3) ; v1(40,58.3) 41.92,58.3 ; v1(40,58.3) 38.08,58.3 ; 9.7,189.84 v3(9.7,188.55) 9.49,188.55 ; 10.4,150.71 v3(10.4,150.9) 8.79,150.9 ; 71.45,94.66 v3(71.45,93.55) 71.66,93.55 ; 58.86,150.9 X12.1 61.74,150.9 ; 65.09,144.2 C24.2 66.5,145.49 ; 33,93.91 C201.2 31.94,92.8 ; 45.04,132.35 v3(46.45,132.35) 47.86,132.35 ; X15.4 21.92,8.12 ; X15.4 24.12,5.92 ; X15.4 21.92,3.72 ; X15.4 19.72,5.92 ; 24.92,150 v3(23,150) 23,149.76 ; 10,65.3 GND.1 ; GND.1 10,68.3 ; GND.1 8.5,66.8 ; GND.1 11.5,66.8 ; 40.7,118.25 G2.4 ; G2.4 42.15,116.8 ; G2.4 43.6,118.25 ; G2.4 42.15,119.7 ; 68.5,118.24 C32.2 67.09,116.95 ; 22.56,190.6 R82.2 19.74,190.6 ; 71.28,199.12 C64.2 73.2,200.54 ; 61,145.69 C41.2 59.59,144.4 ; 12.85,195.28 v3(12.85,195.65) ; v3(12.85,195.65) 12.85,195.89 ; v3(12.85,195.65) 13.09,195.65 ; v3(12.85,195.65) 12.37,195.65 ; 71.3,190.9 v2(71.7,190.9) ; v2(71.7,190.9) 71.7,190.5 ; v2(71.7,190.9) 71.7,191.34 ; v2(71.7,190.9) 72.11,190.9 ; 46.95,157.54 v3(46.95,157.85) ; v3(46.95,157.85) 46.69,157.85 ; v3(46.95,157.85) 47.49,157.85 ; v3(46.95,157.85) 46.95,158.11 ; v2(87.15,127.25) 87.37,127.25 ; v2(87.15,127.25) 87.15,127.53 ; v2(87.15,127.25) 86.58,127.25 ; v2(87.15,127.25) 87.15,127.03 ; 84.35,118.21 v2(84.35,118.05) 83.31,118.05 ; v3(66.7,154.45) 66.7,154.76 ; v3(66.7,154.45) 66.7,154.1 ; v3(66.7,154.45) 66.2,154.45 ; v3(66.7,154.45) 67.02,154.45 ; 42.76,131.5 C12.1 39.94,131.5 ; X14.3 16.08,8.12 ; X14.3 18.28,5.92 ; X14.3 13.88,5.92 ; X14.3 16.08,3.72 ; 79.96,128.25 C37.2 81.25,129.66 ; 88.51,48.4 C184.2 85.69,48.4 ; 79.86,138.25 v3(80.15,138.25) ; v3(80.15,138.25) 80.15,139.66 ; v3(80.15,138.25) 80.15,136.84 ; 76.29,86.35 C75.2 74.87,88.27 ; 81.85,154.34 v2(81.85,154.65) ; v2(81.85,154.65) 82.71,154.65 ; v2(81.85,154.65) 80.59,154.65 ; 21.81,93 C132.2 20.7,91.94 ; X16.3 48.08,8.12 ; X16.3 48.08,3.72 ; X16.3 50.28,5.92 ; X16.3 45.88,5.92 ; 61.88,5.92 X17.3 ; X17.3 64.08,3.72 ; X17.3 64.08,8.12 ; X17.3 66.28,5.92 ; 24.1,187.16 v3(24.1,185.75) 24.29,185.75 ; 29.54,9.6 X15.2 ; X15.2 30.94,11 ; X15.2 29.54,12.4 ; 81.15,118.84 C27.2 ; C27.2 79.86,120.25 ; C27.2 81.15,121.66 ; 89.49,31.54 X18.2 92.31,31.54 ; 85.69,49.5 v3(87.1,49.5) ; v3(87.1,49.5) 87.1,49.69 ; v3(87.1,49.5) 88.51,49.5 ; X14.2 14.94,11 ; X14.2 13.54,9.6 ; X14.2 13.54,12.4 ; 23.9,179.95 v4(24.2,179.95) ; v4(24.2,179.95) 24.2,179.48 ; v4(24.2,179.95) 24.55,179.95 ; v4(24.2,179.95) 24.2,180.24 ; v3(64.35,163.4) 64.6,163.4 ; v3(64.35,163.4) 64.12,163.4 ; v3(64.35,163.4) 64.35,163.63 ; v3(64.35,163.4) 64.35,163.06 ; 79.79,35.4 C78.1 81.2,36.69 ; 91.5,192.76 v1(91.5,193.11) ; v1(91.5,193.11) 91.29,193.11 ; v1(91.5,193.11) 91.5,193.32 ; v1(91.5,193.11) 92,193.11 ; 81.44,188.7 C386.2 82.85,187.41 ; 82.01,160.85 C62.2 79.89,160.85 ; X17.4 53.92,8.12 ; X17.4 53.92,3.72 ; X17.4 56.12,5.92 ; X17.4 51.72,5.92 ; v3(72.3,36.5) 73.71,36.5 ; v3(72.3,36.5) 70.89,36.5 ; v3(72.3,36.5) 72.3,36.69 ; 76.84,116.95 C33.2 79.66,116.95 ; 34.5,195.21 C382.2 33.21,193.8 ; 46.95,169.36 v3(46.95,168.25) 46.69,168.25 ; v2(10.25,28.45) 10.25,28.78 ; v2(10.25,28.45) 10.58,28.45 ; v2(10.25,28.45) 9.78,28.45 ; v2(10.25,28.45) 10.25,28.07 ; 54,83.16 X10.1 52.56,84.6 ; 13.8,132.26 X11.1 ; X11.1 15.24,133.7 ; X11.1 12.36,133.7 ; X11.1 13.8,135.14 ; 67.91,144.05 v2(67.65,144.05) 67.65,145.49 ; 19.37,45.17 X7.10 20.82,46.62 ; 36.09,83 C119.2 37.2,81.94 ; 62.61,116.5 C26.2 59.79,116.5 ; 80.45,40.87 v3(82.7,40.87) 82.7,41.04 ; 77.76,110.85 v2(78.15,110.85) ; v2(78.15,110.85) 78.37,110.85 ; v2(78.15,110.85) 78.15,110.39 ; v2(78.15,110.85) 78.15,111.07 ; X9.1 65.7,41.84 ; X9.1 65.7,38.96 ; X9.1 67.14,40.4 ; X9.1 64.26,40.4 ; 51.18,65.9 v3(53.1,65.9) ; v3(53.1,65.9) 53.1,65.66 ; v3(53.1,65.9) 55.02,65.9 ; 68.05,163.54 C57.2 ; C57.2 66.99,164.65 ; C57.2 69.11,164.65 ; 51.18,67.08 C143.2 55.02,67.08 ; 20,88.94 C190.2 21.11,90 ; X15.3 34.28,5.92 ; X15.3 29.88,5.92 ; X15.3 32.08,3.72 ; X15.3 32.08,8.12 ; v3(8.15,145.85) 8.15,146.28 ; v3(8.15,145.85) 7.73,145.85 ; v3(8.15,145.85) 8.39,145.85 ; v3(8.15,145.85) 8.15,145.61 ; 84.45,111.11 v2(84.45,112.75) 84.19,112.75 ; 51.3,83.62 v3(51.3,84) ; v3(51.3,84) 51.3,84.39 ; v3(51.3,84) 51,84 ; v3(51.3,84) 51.76,84 ; 34.5,192.39 v1(34.5,192.6) 33.21,192.6 ; 77.25,126.4 v3(77.5,126.4) ; v3(77.5,126.4) 78.03,126.4 ; v3(77.5,126.4) 77.5,126.15 ; v3(77.5,126.4) 77.5,126.72 ; 46.69,164.25 v3(46.95,164.25) 46.95,164.96 ; 23.9,178.15 v4(24.2,178.15) ; v4(24.2,178.15) 24.57,178.15 ; v4(24.2,178.15) 24.2,178.6 ; v4(24.2,178.15) 24.2,177.78 ; 50.85,134.66 C25.2 49.56,132.05 ; v2(26.25,28.45) 26.7,28.45 ; v2(26.25,28.45) 26.25,28.8 ; v2(26.25,28.45) 26.25,28.06 ; v2(26.25,28.45) 25.9,28.45 ; 70.89,35.4 C71.1 73.71,35.4 ; 43.06,138.75 C44.2 40.24,138.75 ; 23.86,100.4 v1(22.5,100.4) 22.5,100.19 ; v3(51.85,24.5) 51.85,25.91 ; v3(51.85,24.5) 51.61,24.5 ; v3(51.85,24.5) 51.85,23.09 ; 15.81,150.9 v3(14.4,150.9) 14.4,150.71 ; 64.55,87.94 v2(64.55,89.05) 64.91,89.05 ; 46.59,152.7 v4(46.44,152.7) 46.44,152.39 ; 80.2,136.66 v3(80.2,135.25) 79.96,135.25 ; 10.79,120.8 v3(12.2,120.8) 12.2,120.99 ; 47.75,164.96 C50.2 46.69,163.85 ; 55.21,66.3 v4(55.41,66.3) 55.41,66.51 ; 81.25,136.66 C38.2 81.25,133.84 ; 41.92,59.38 C218.1 38.08,59.38 ; 79.1,38.19 C182.2 77.81,39.6 ; 67.35,163.54 v2(67.35,164.25) 66.99,164.25 ; 40.4,77.06 C197.2 39.29,76 ; 79.04,61.29 X3.2 ; X3.2 81.86,61.29 ; X3.2 80.45,62.7 ; 20.9,23.09 C157.2 20.9,25.91 ; 22.65,197.45 v3(22.65,197.7) ; v3(22.65,197.7) 22.9,197.7 ; v3(22.65,197.7) 22.65,197.97 ; v3(22.65,197.7) 22.07,197.7 ; 13.18,121.6 v3(15.1,121.6) ; v3(15.1,121.6) 17.02,121.6 ; v3(15.1,121.6) 15.1,121.84 ; X16.2 46.94,11 ; X16.2 45.54,12.4 ; X16.2 45.54,9.6 ; 52.9,23.09 C173.2 52.9,25.91 ; 82.01,162.25 C61.2 79.89,162.25 ; 61.54,9.6 X17.2 ; X17.2 62.94,11 ; X17.2 61.54,12.4 ; 64.66,80.95 C81.2 65.95,79.54 ; 81.54,195.8 C384.2 82.95,194.51 ; 84.6,118.21 C35.2 83.31,116.8 ; 84.19,112.4 R10.1 ; R10.1 87.01,112.4 ; R10.1 85.6,111.11 ; 94.9,202.09 v3(94.9,202.4) ; v3(94.9,202.4) 95.43,202.4 ; v3(94.9,202.4) 94.9,202.66 ; v3(94.9,202.4) 94.64,202.4 ; 37.92,3.72 X16.4 ; X16.4 37.92,8.12 ; X16.4 35.72,5.92 ; X16.4 40.12,5.92 ; 36.9,26.01 C165.2 36.9,23.19 ; 56.08,59.48 C141.2 54.66,61.4 ; v3(59.7,207.8) 59.7,208.19 ; v3(59.7,207.8) 60.16,207.8 ; v3(59.7,207.8) 59.49,207.8 ; v3(59.7,207.8) 59.7,207.59 ; 12.4,58.21 R68.2 12.4,55.39 ; 81.28,36.58 C185.2 84.4,35.16 ; 25.36,93 v1(25,93) 25,93.91 ; 18.23,150 v3(19.9,150) 19.9,149.76 ; 10.2,150.71 C135.2 8.79,152 ; 28.81,101.4 R120.2 30.1,102.81 ; 18,66.89 v1(18,68) 17.64,68 ; 79.65,92.06 v3(79.65,92.35) 78.24,92.35 ; 49.4,186.16 X13.1 ; X13.1 49.4,189.04 ; X13.1 50.84,187.6 ; 82.46,144 C39.2 79.64,144 ; 46.99,147.85 C43.2 45.57,145.93 ; 81.15,136.84 C28.2 81.15,139.66 ; 71.3,146.19 C40.2 72.71,144.9 ; 70.5,77.85 v3(72.75,77.85) 72.75,76.09 ; 78.65,180.51 v2(78.65,178.75) 78.34,178.75 ; 67.45,158.74 v3(67.45,159.45) 67.19,159.45 ; 82.4,3.96 X6.9 ; X6.9 84.58,6.14 ; X6.9 86.76,3.96 ; 17.54,100.5 v1(18.6,100.5) 18.6,100.19 ; 79.55,165.54 C60.2 80.61,166.65 ; 43.26,120.05 C17.1 44.55,118.64 ; 47.07,138.03 C45.2 43.23,138.03 ; 30.3,30.91 v3(30.3,32.2) 30.51,32.2
  BOTTOM w1: C43.2 45.57,148.84 v4(46.44,149.7) ; C42.2 46.4,152.7 v4(46.44,152.7)
  vias: v1(16.8,58.7) v1(57.9,191.8) v2(8.3,26.45) v2(10.25,26.45) v2(24.3,26.45) v2(25.27,27.45) v2(26.25,26.45) v2(41.27,27.45) v2(42.25,26.45) v2(56.3,26.45) v2(57.27,27.45) v2(58.25,28.45) v2(58.25,26.45) v2(81.1,192.9) v2(82.1,184.3) v3(1.5,11.5) v3(1.5,10.5) v3(1.5,9.5) v3(1.5,8.5) v3(1.5,7.5) v3(1.5,6.5) v3(1.5,5.5) v3(1.5,4.5) v3(1.5,3.5) v3(1.5,2.5) v3(1.5,1.5) v3(12.85,197.7) v3(12.85,193.6) v3(12.85,191.55) v3(16.4,216.3) v3(22.65,199.8) v3(22.65,195.65) v3(22.65,193.6) v3(22.65,191.55) v3(35.1,50.8) v3(37.3,50.8) v3(37.3,46.8) v3(54.6,143.9) v3(54.7,170.8) v3(61.8,147.8) v3(62,95.2) v3(62.1,207.8) v3(63.7,152) v3(64.25,183.55) v3(65,87.8) v3(68.5,200.4) v3(69.1,156.8) v3(69.65,126.45) v3(69.65,88.35) v3(77.35,95.25) v3(79.25,130.45) v3(97.5,11.5) v3(97.5,10.5) v3(97.5,9.5) v3(97.5,8.5) v3(97.5,7.5) v3(97.5,6.5) v3(97.5,5.5) v3(97.5,4.5) v3(97.5,3.5) v3(97.5,2.5) v3(97.5,1.5)
